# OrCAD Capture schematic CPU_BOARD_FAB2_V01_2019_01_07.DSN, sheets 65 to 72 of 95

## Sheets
65 053 COM-E_TYPE7_AB_1: size B
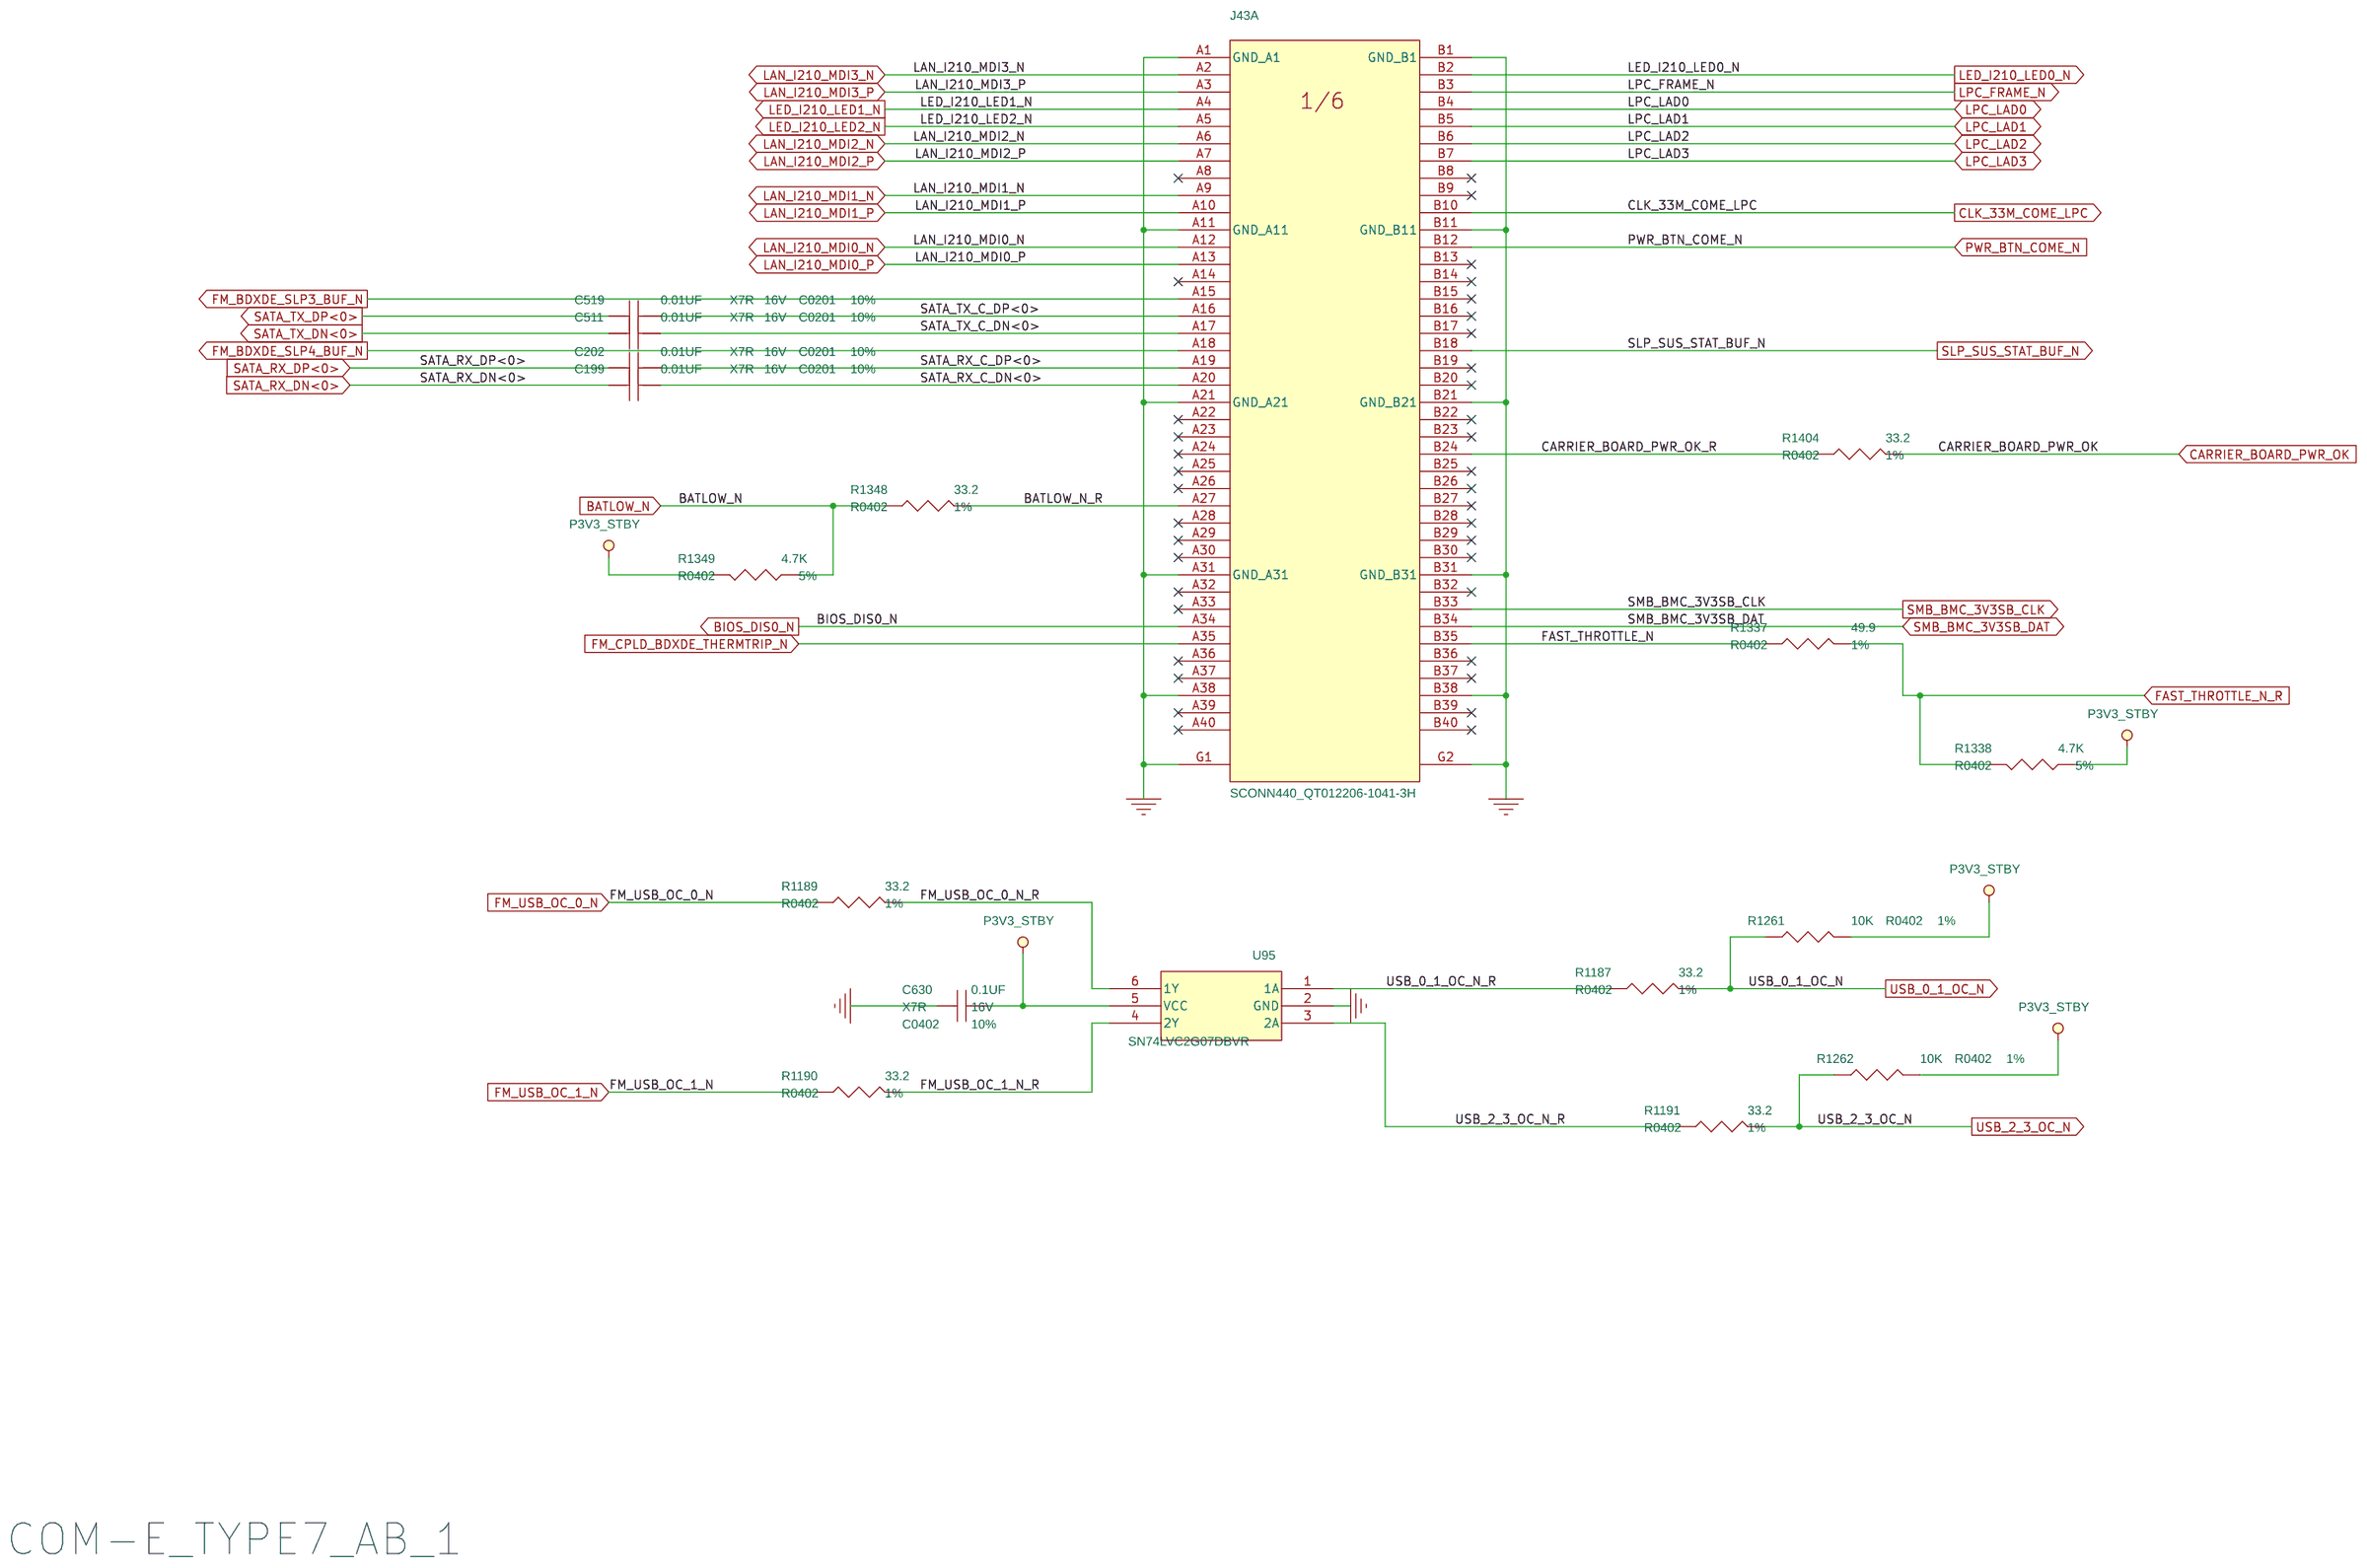
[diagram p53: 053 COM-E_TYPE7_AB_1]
66 055 COM-E_TYPE7_CD_1: size B
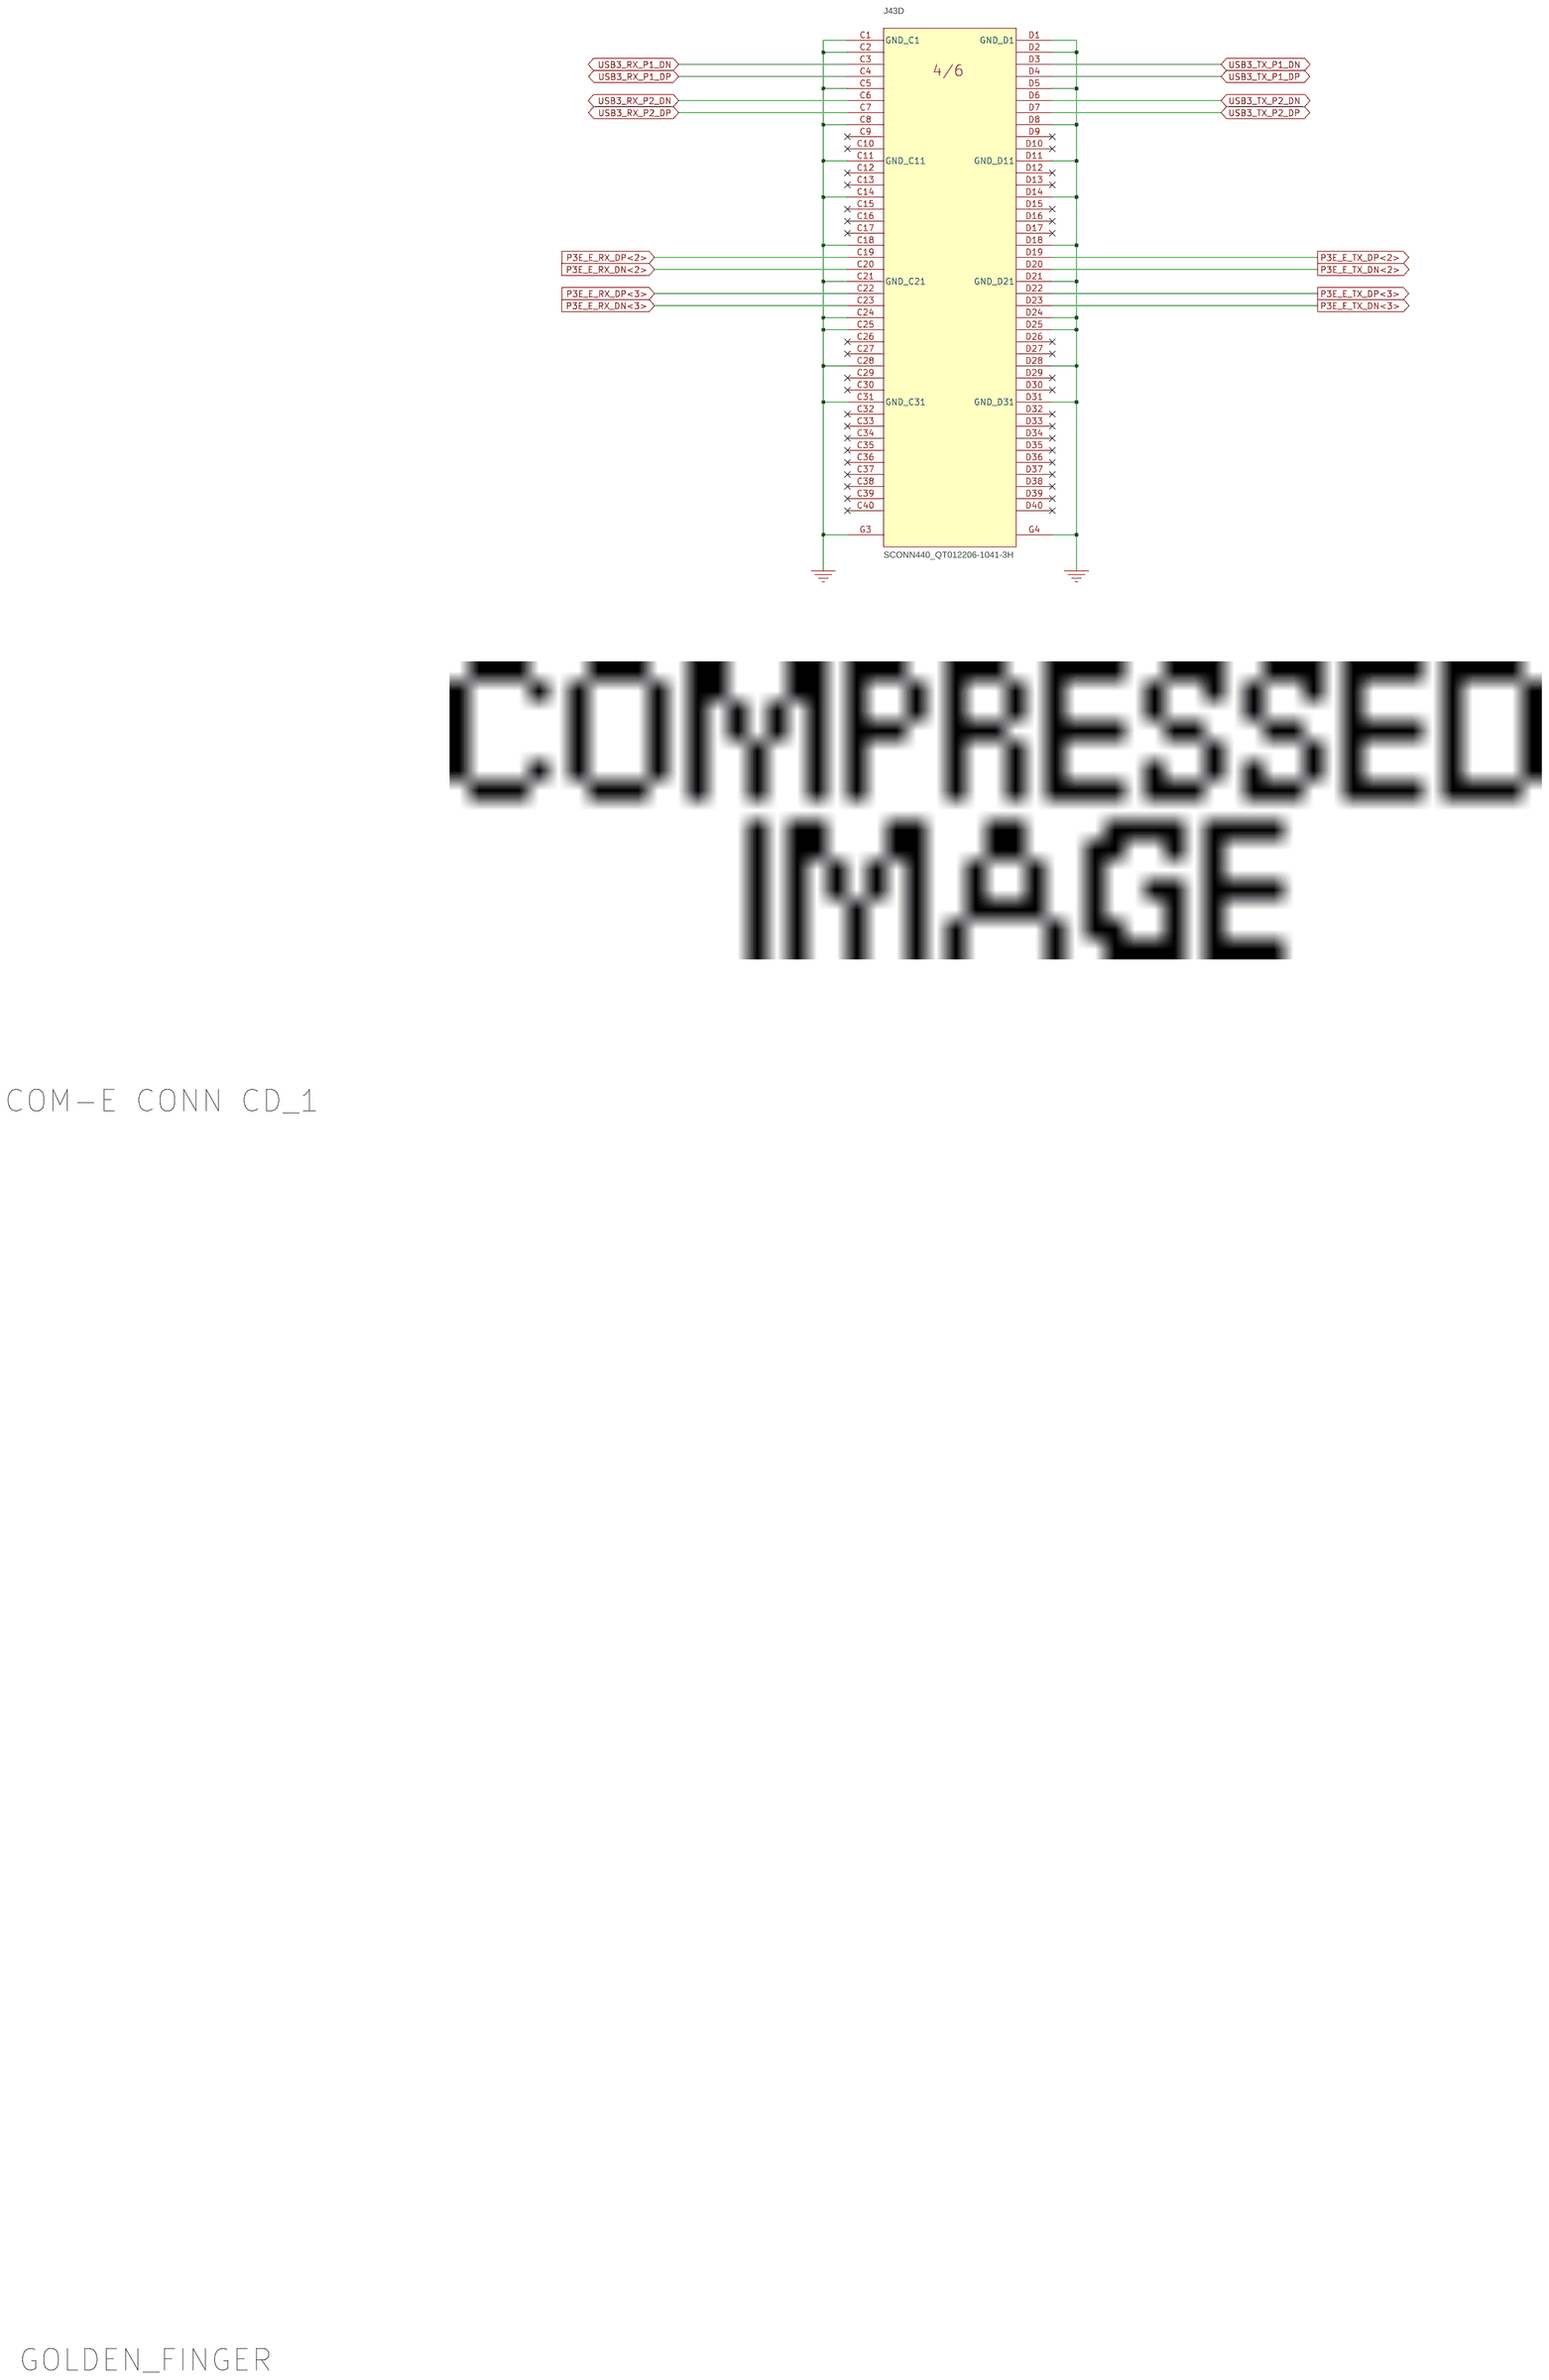
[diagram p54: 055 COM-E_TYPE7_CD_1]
67 057 LEVEL_SHIFT: size B
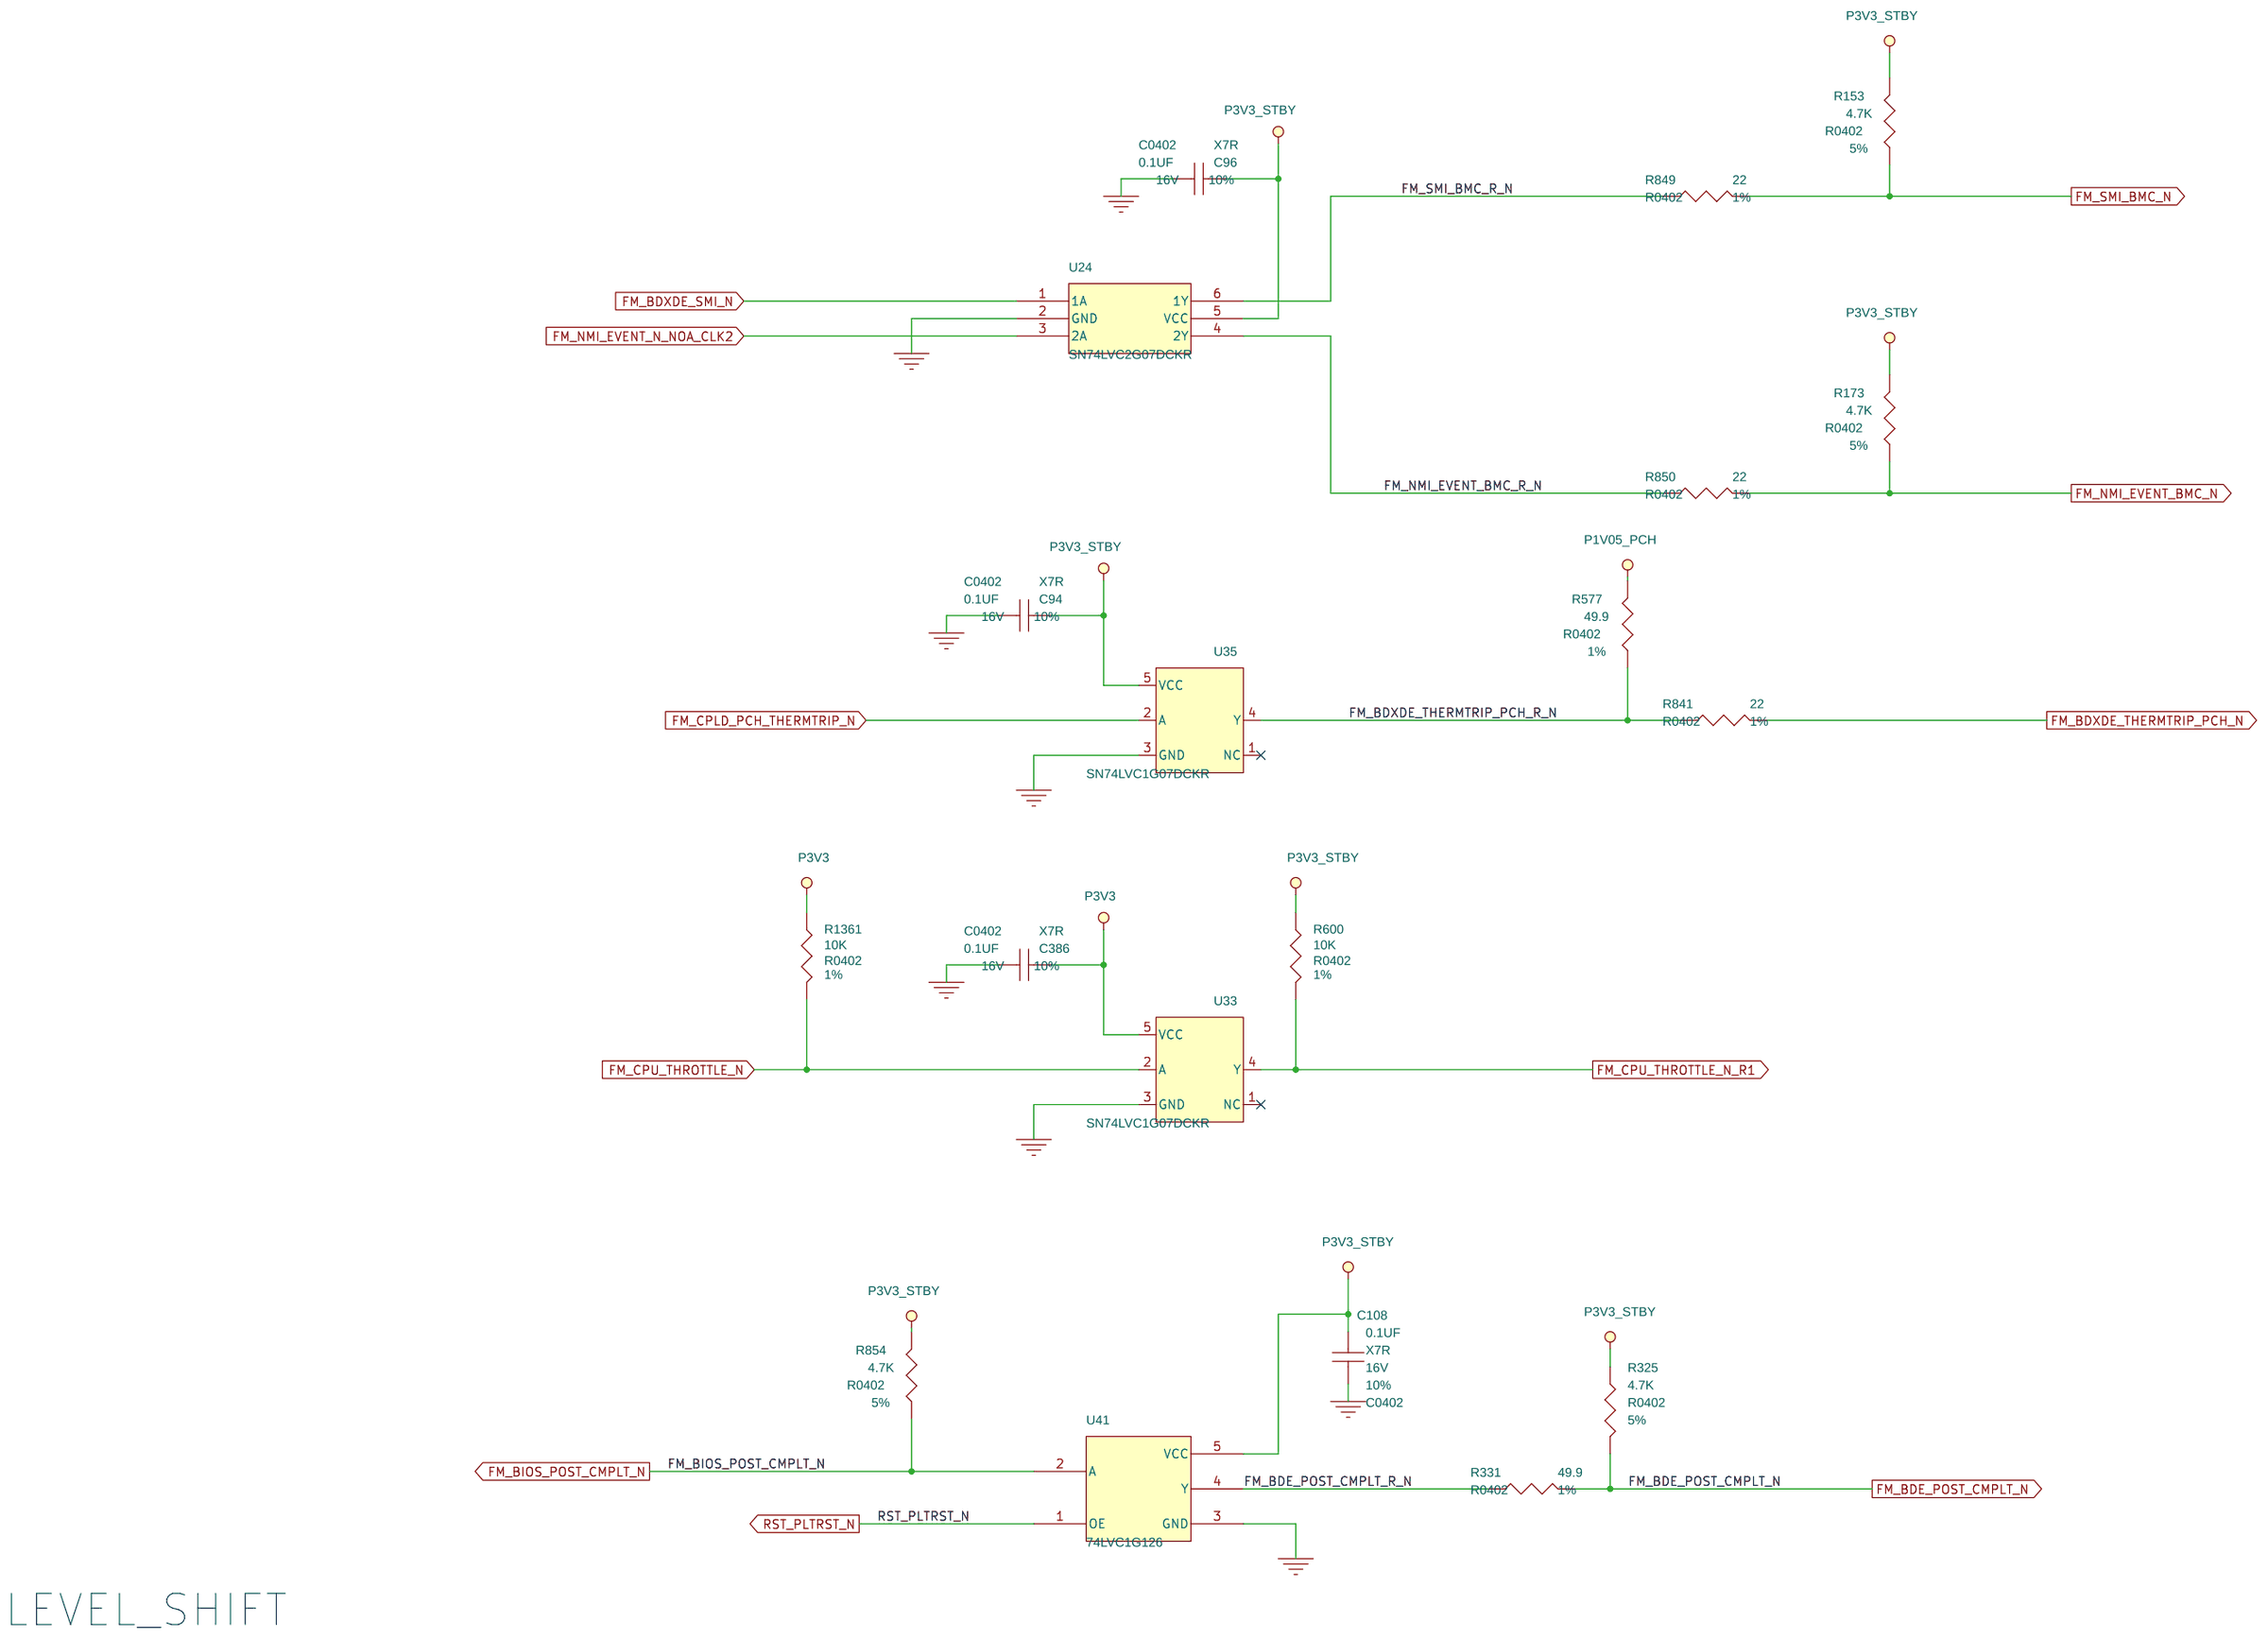
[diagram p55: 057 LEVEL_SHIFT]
68 058 SYS_SENSOR: size B
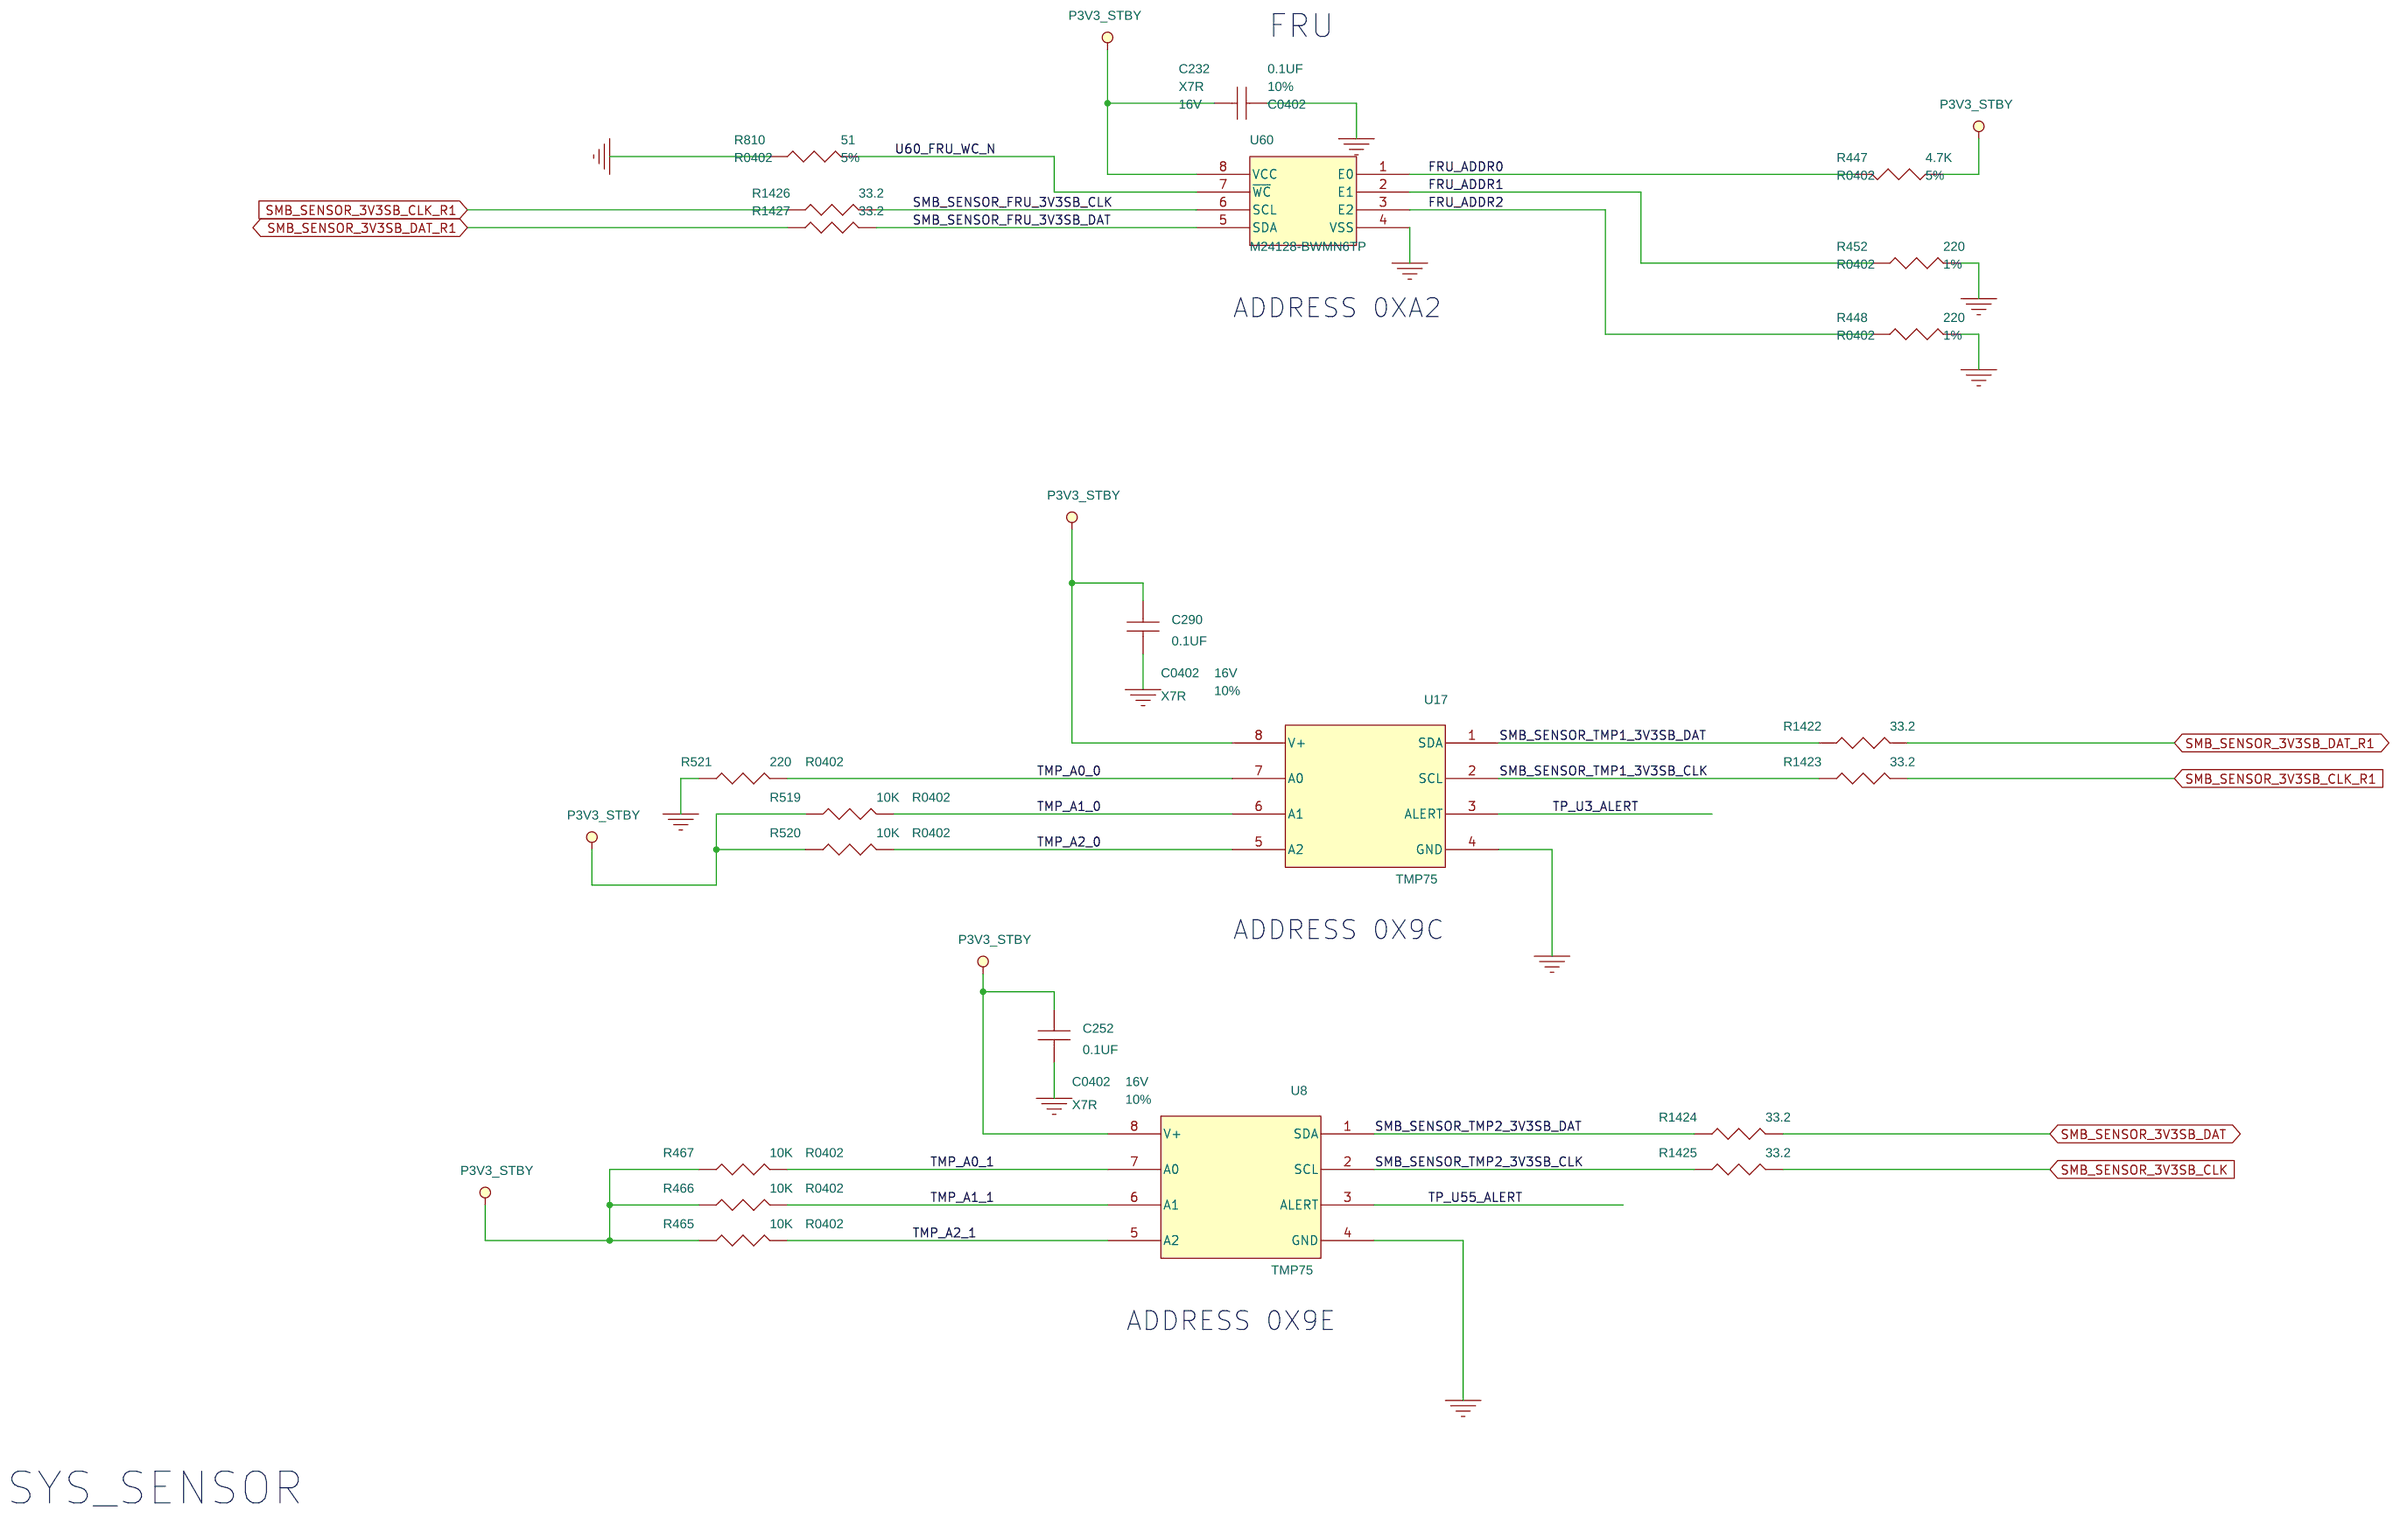
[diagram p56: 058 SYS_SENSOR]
69 059 PWR_SYSRST_BUTTON: size B
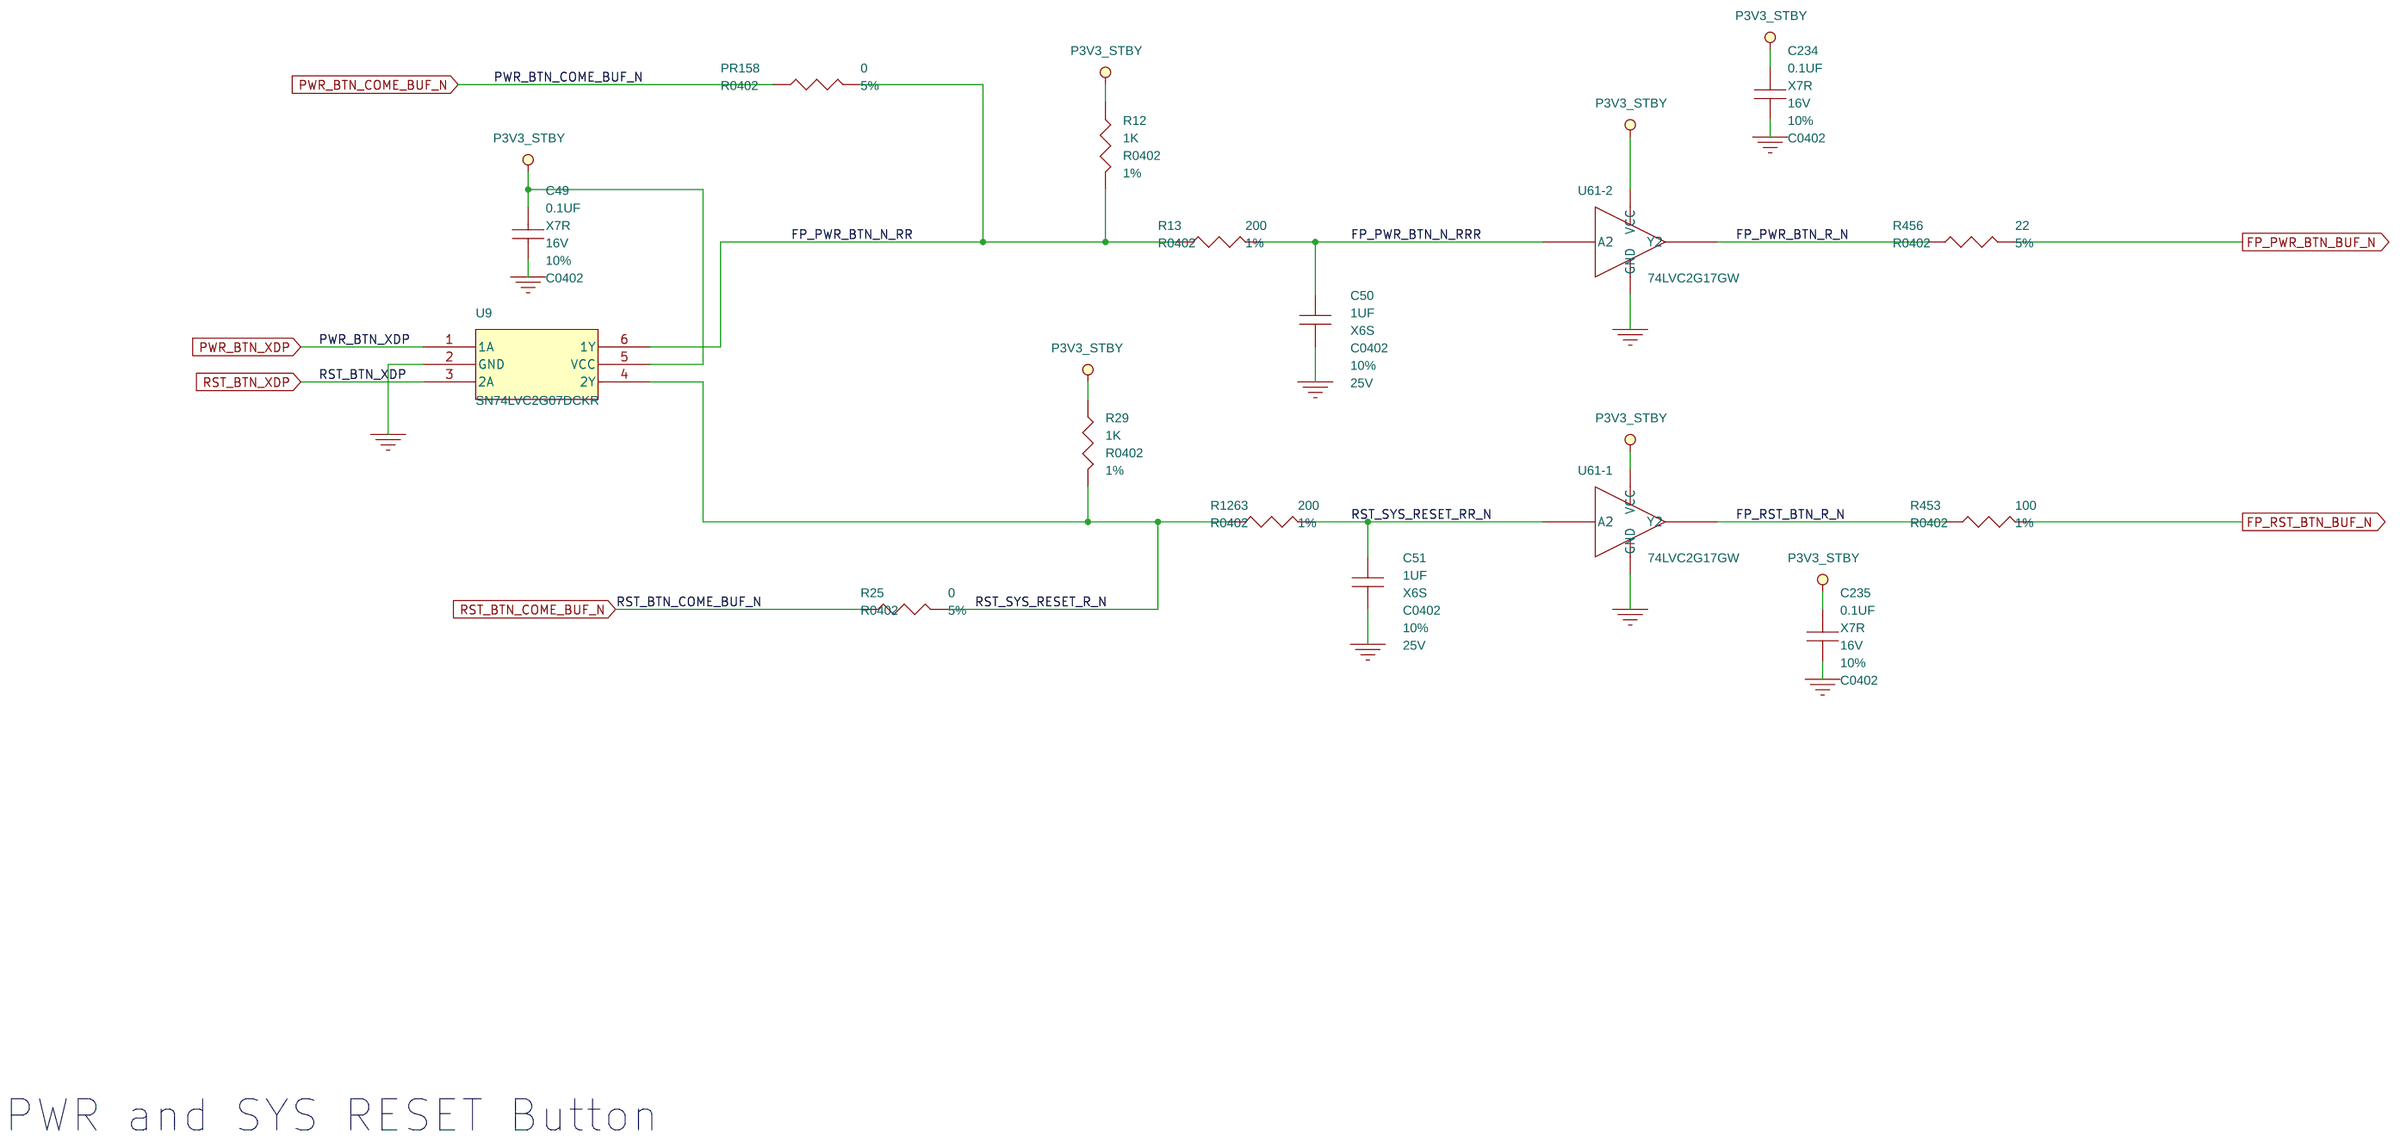
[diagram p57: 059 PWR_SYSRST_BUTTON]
70 060 DEBUG UART: size B
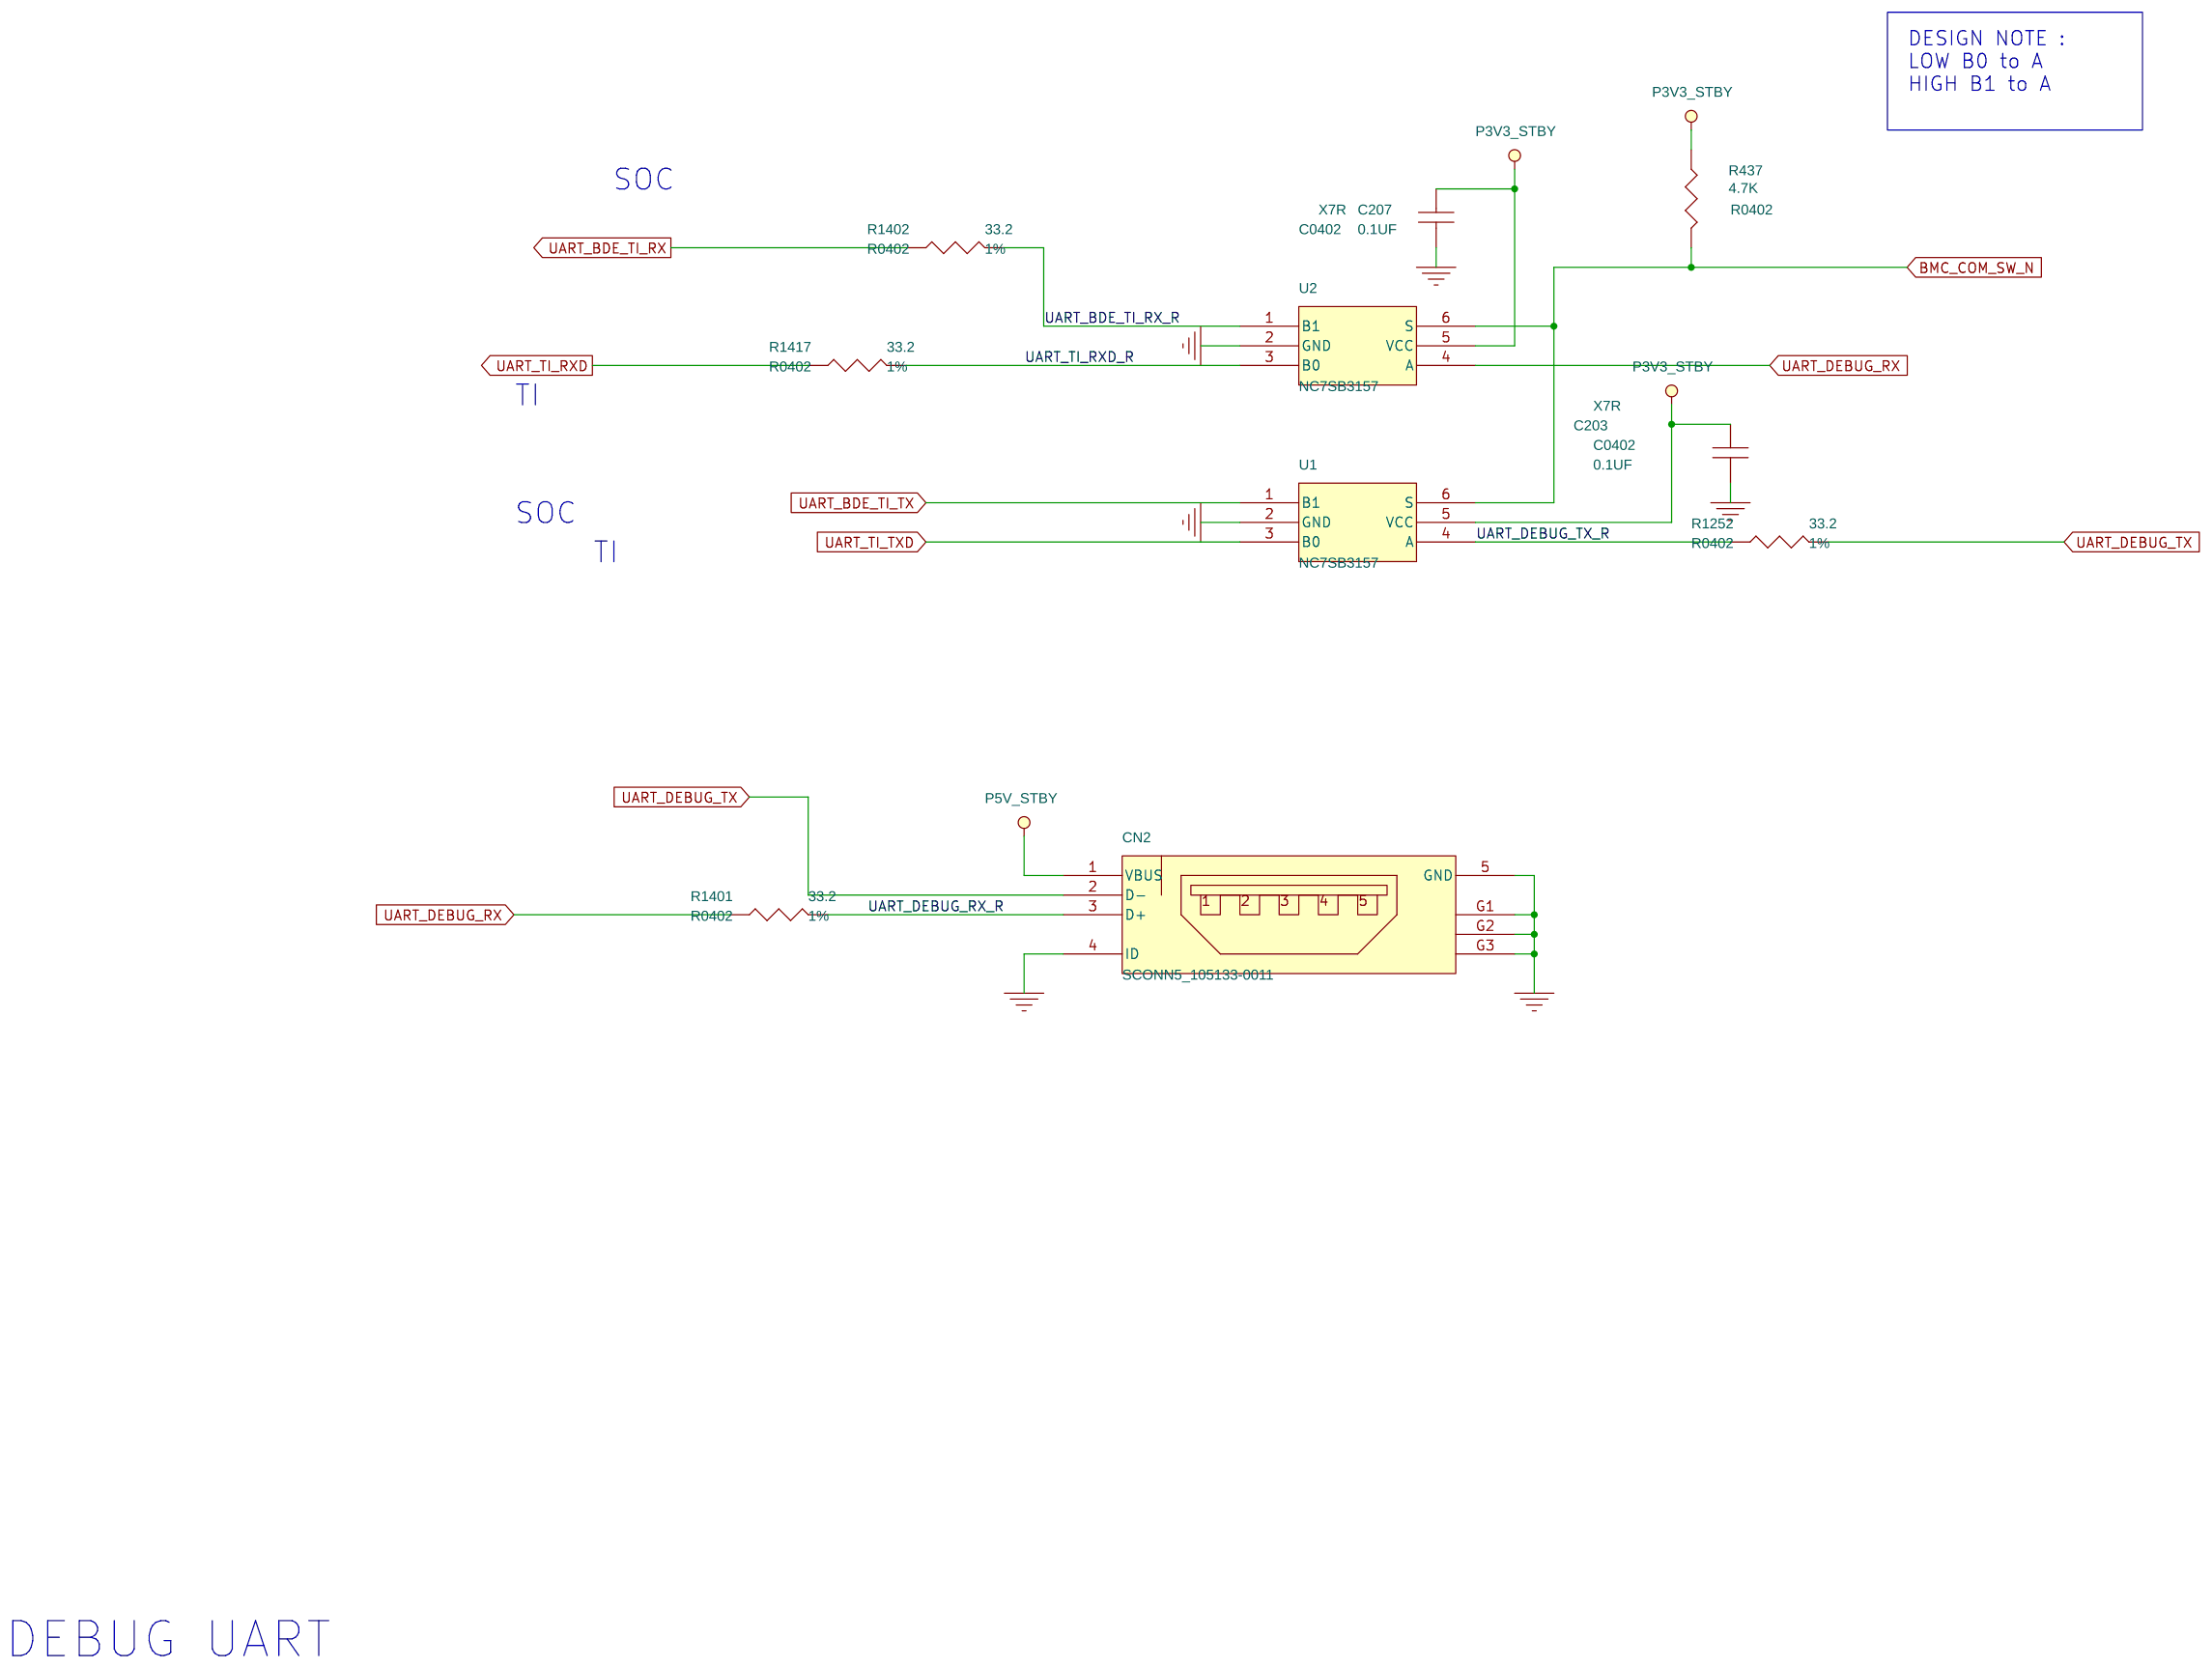
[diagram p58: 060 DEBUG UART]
71 061 SNOWFLAKE_1: size B
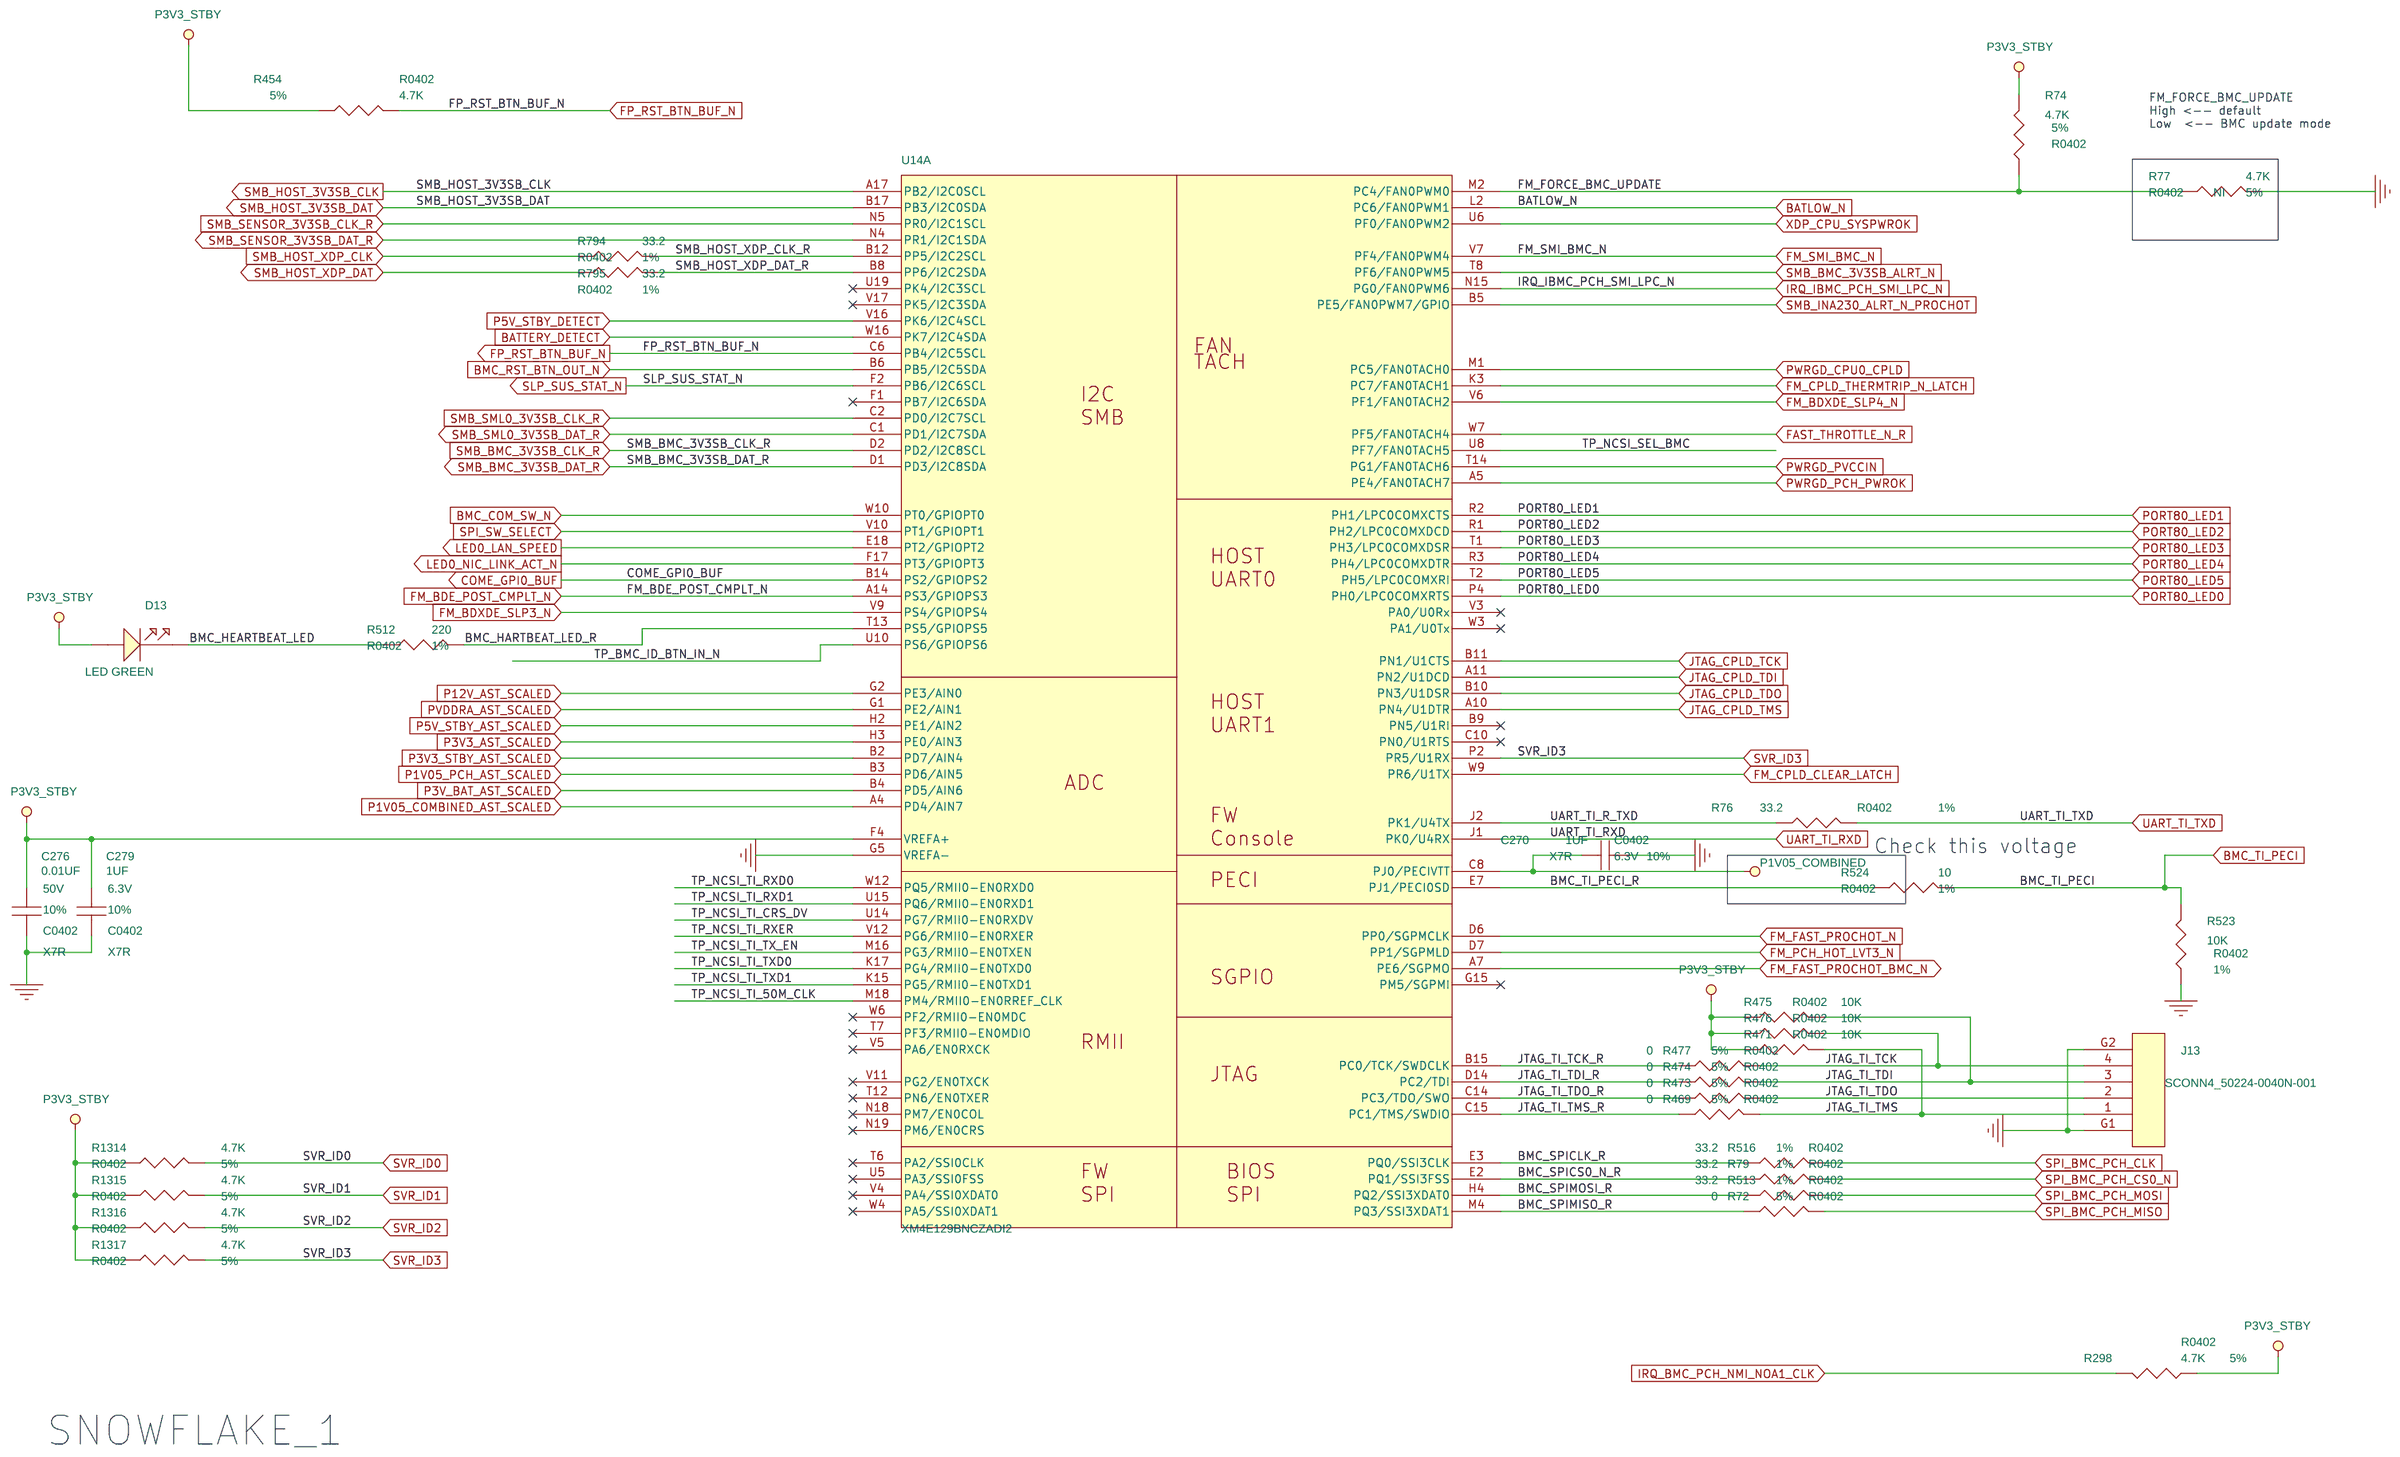
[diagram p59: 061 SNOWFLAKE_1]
72 062 SNOWFLAKE_2: size B
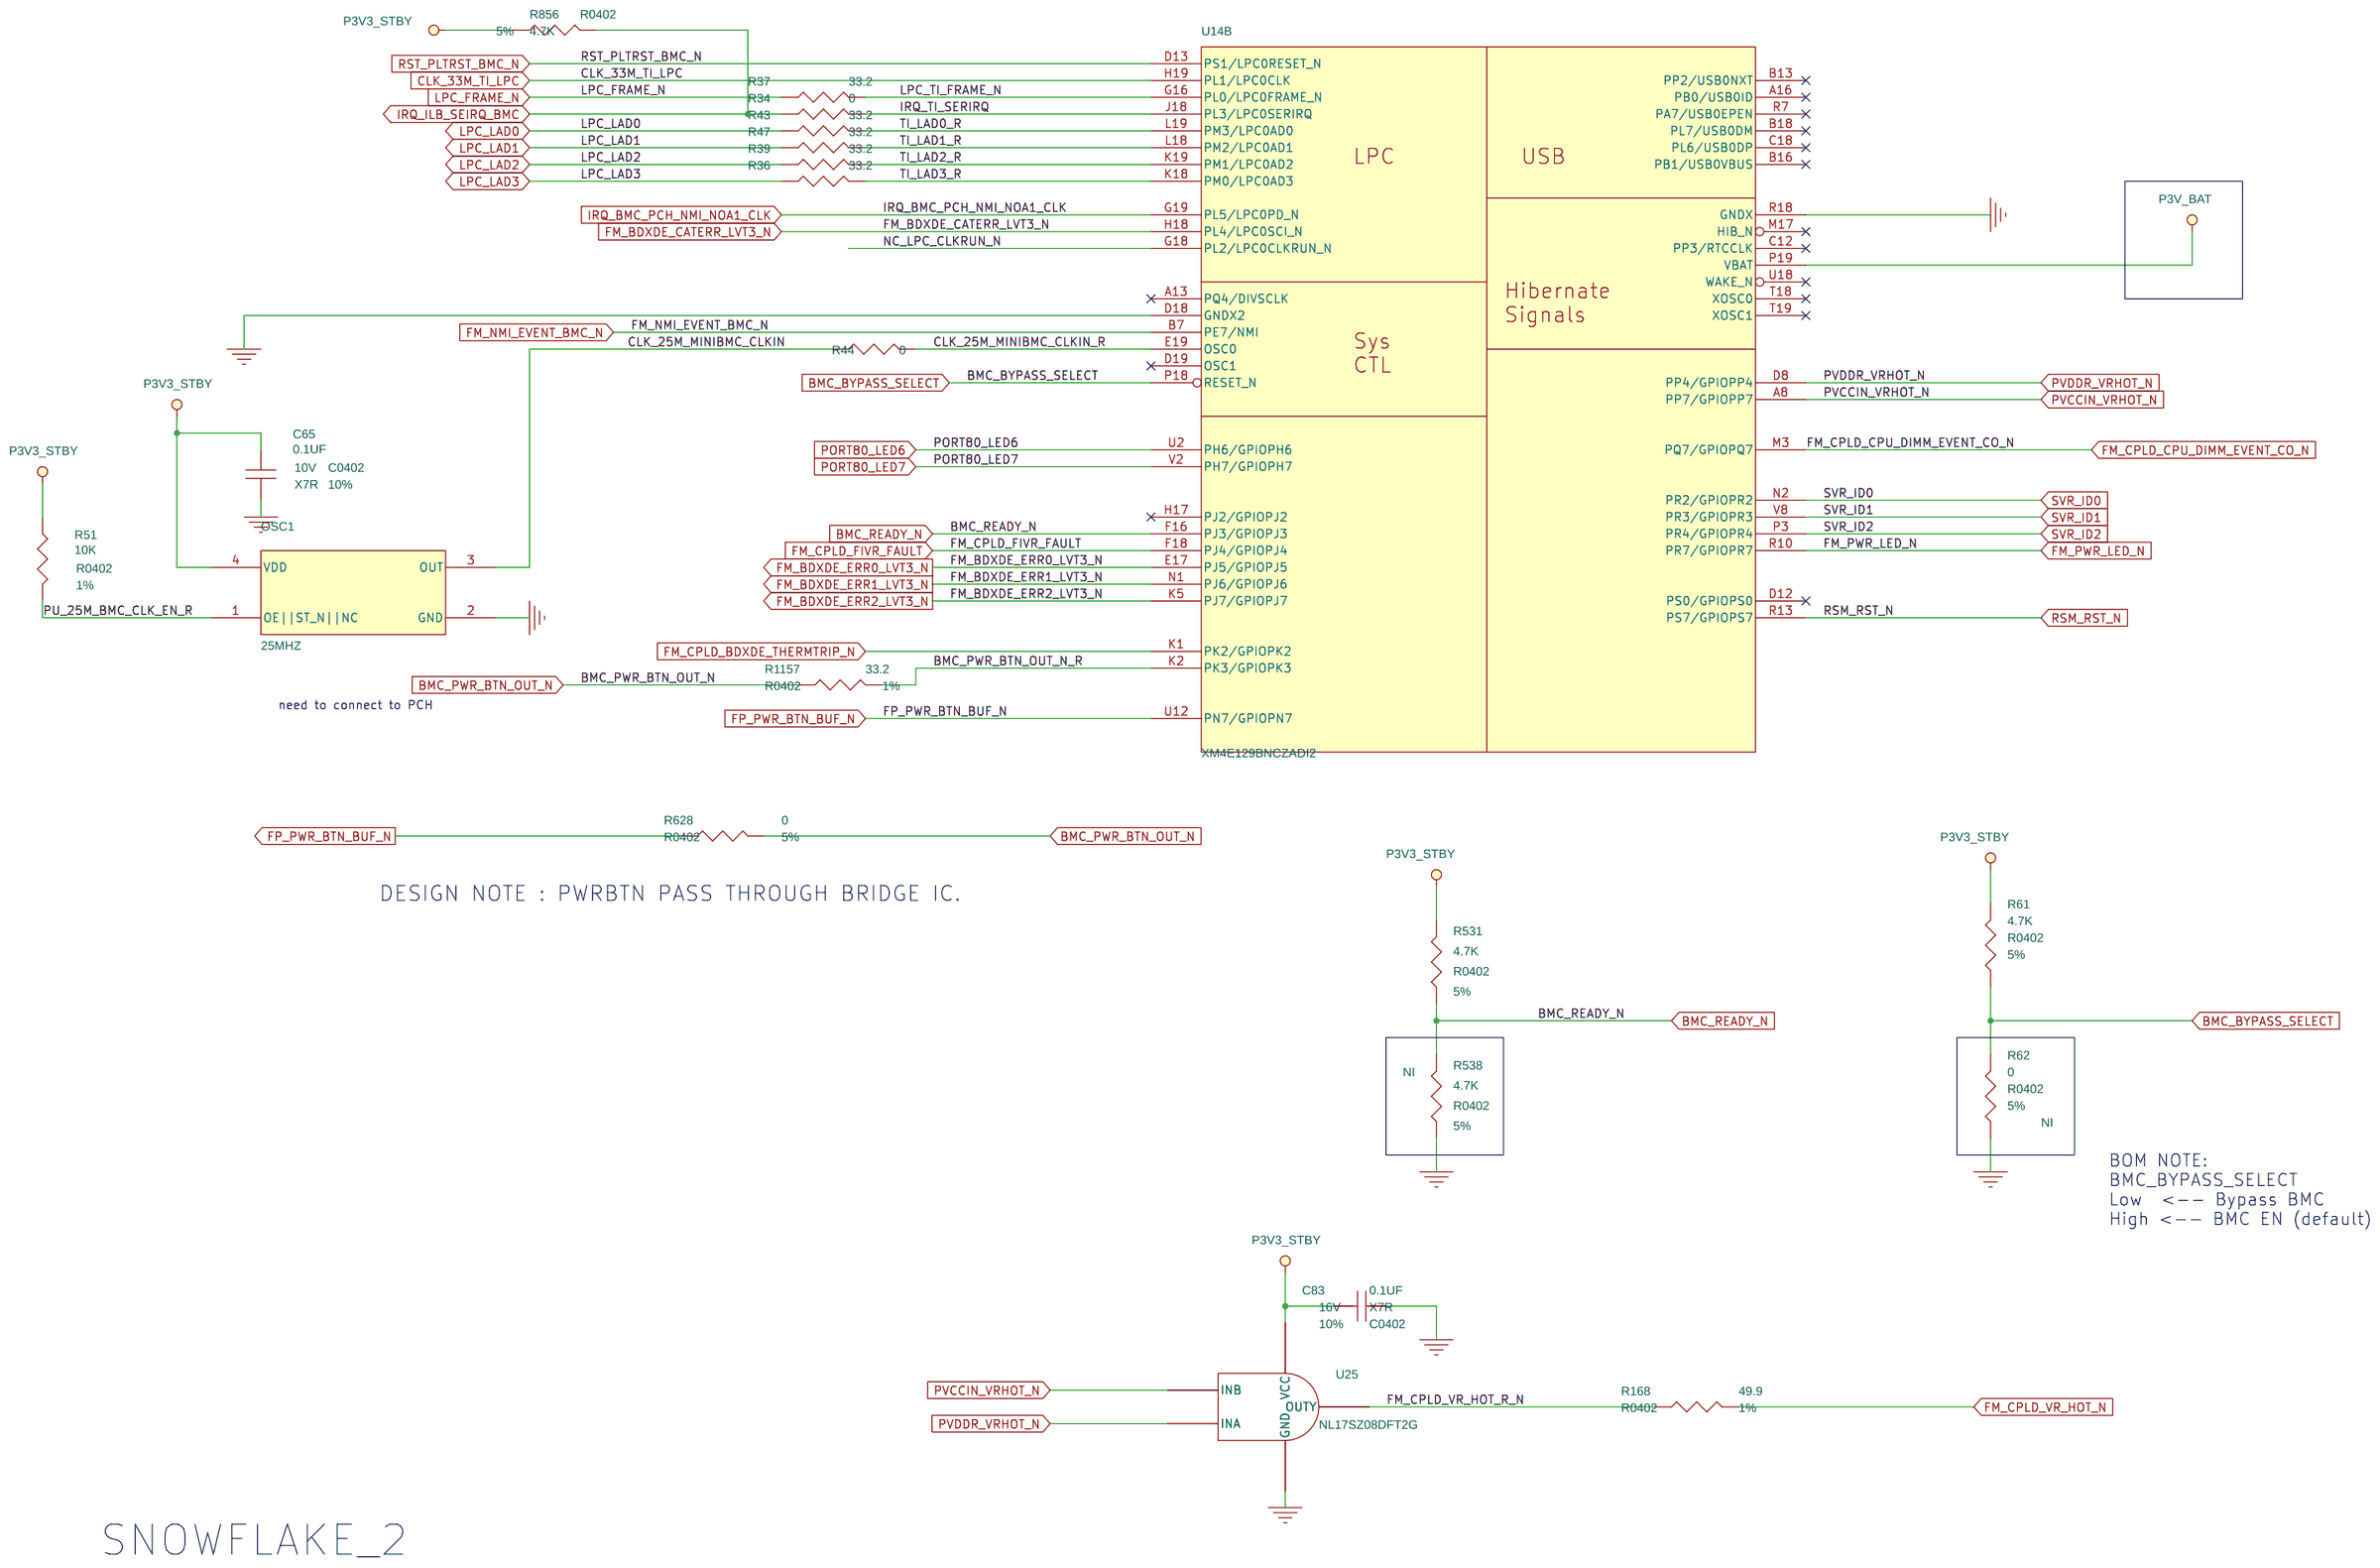
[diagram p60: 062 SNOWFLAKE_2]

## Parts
sheet 053 COM-E_TYPE7_AB_1
C199  0.01UF  [C0201]
C202  0.01UF  [C0201]
C511  0.01UF  [C0201]
C519  0.01UF  [C0201]
C630  0.1UF  [C0402]
R1187  33.2  [R0402]
R1189  33.2  [R0402]
R1190  33.2  [R0402]
R1191  33.2  [R0402]
R1261  10K  [R0402]
R1262  10K  [R0402]
R1337  49.9  [R0402]
R1338  4.7K  [R0402]
R1348  33.2  [R0402]
R1349  4.7K  [R0402]
R1404  33.2  [R0402]
U95  SN74LVC2G07DBVR  [SOT23-6XD]
sheet 055 COM-E_TYPE7_CD_1
J43  SCONN440_QT012206-1041-3H  [CON_440S4H4D4S_P0-5_LUH]  (sections A,B,C,D,E,F)
sheet 057 LEVEL_SHIFT
C94  0.1UF  [C0402]
C96  0.1UF  [C0402]
C108  0.1UF  [C0402]
C386  0.1UF  [C0402]
R153  4.7K  [R0402]
R173  4.7K  [R0402]
R325  4.7K  [R0402]
R331  49.9  [R0402]
R577  49.9  [R0402]
R600  10K  [R0402]
R841  22  [R0402]
R849  22  [R0402]
R850  22  [R0402]
R854  4.7K  [R0402]
R1361  10K  [R0402]
U24  SN74LVC2G07DCKR  [SC70-6]
U33  SN74LVC1G07DCKR  [SC70-5XB]
U35  SN74LVC1G07DCKR  [SC70-5XB]
U41  74LVC1G126  [SOT353_Q]
sheet 058 SYS_SENSOR
C232  0.1UF  [C0402]
C252  0.1UF  [C0402]
C290  0.1UF  [C0402]
R447  4.7K  [R0402]
R448  220  [R0402]
R452  220  [R0402]
R465  10K  [R0402]
R466  10K  [R0402]
R467  10K  [R0402]
R519  10K  [R0402]
R520  10K  [R0402]
R521  220  [R0402]
R810  51  [R0402]
R1422  33.2  [R0402]
R1423  33.2  [R0402]
R1424  33.2  [R0402]
R1425  33.2  [R0402]
R1426  33.2  [R0402]
R1427  33.2  [R0402]
U8  TMP75  [MSOP8]
U17  TMP75  [MSOP8]
U60  M24128-BWMN6TP  [SOIC8XH]
sheet 059 PWR_SYSRST_BUTTON
C49  0.1UF  [C0402]
C50  1UF  [C0402]
C51  1UF  [C0402]
C234  0.1UF  [C0402]
C235  0.1UF  [C0402]
PR158  0  [R0402]
R12  1K  [R0402]
R13  200  [R0402]
R25  0  [R0402]
R29  1K  [R0402]
R453  100  [R0402]
R456  22  [R0402]
R1263  200  [R0402]
U9  SN74LVC2G07DCKR  [SC70-6]
U61  74LVC2G17GW  [SOT363]  (sections -1,-2)
sheet 060 DEBUG UART
C203  0.1UF  [C0402]
C207  0.1UF  [C0402]
CN2  SCONN5_105133-0011  [USB1XAY]
R437  4.7K  [R0402]
R1252  33.2  [R0402]
R1401  33.2  [R0402]
R1402  33.2  [R0402]
R1417  33.2  [R0402]
U1  NC7SB3157  [SC70-6]
U2  NC7SB3157  [SC70-6]
sheet 061 SNOWFLAKE_1
C270  1UF  [C0402]
C276  0.01UF  [C0402]
C279  1UF  [C0402]
D13  LED GREEN  [LED2S_0402]
J13  SCONN4_50224-0040N-001  [CON_4S1H2S_P1XC]
R72  0  [R0402]
R74  4.7K  [R0402]
R76  33.2  [R0402]
R77  4.7K  [R0402]
R79  33.2  [R0402]
R298  4.7K  [R0402]
R454  4.7K  [R0402]
R469  0  [R0402]
R471  10K  [R0402]
R473  0  [R0402]
R474  0  [R0402]
R475  10K  [R0402]
R476  10K  [R0402]
R477  0  [R0402]
R512  220  [R0402]
R513  33.2  [R0402]
R516  33.2  [R0402]
R523  10K  [R0402]
R524  10  [R0402]
R794  33.2  [R0402]
R795  33.2  [R0402]
R1314  4.7K  [R0402]
R1315  4.7K  [R0402]
R1316  4.7K  [R0402]
R1317  4.7K  [R0402]
sheet 062 SNOWFLAKE_2
C65  0.1UF  [C0402]
C83  0.1UF  [C0402]
OSC1  25MHZ  [OSC4S_SIT1602BI_2X1-6]
R34  0  [R0402]
R36  33.2  [R0402]
R37  33.2  [R0402]
R39  33.2  [R0402]
R43  33.2  [R0402]
R44  0  [R0402]
R47  33.2  [R0402]
R51  10K  [R0402]
R61  4.7K  [R0402]
R62  0  [R0402]
R168  49.9  [R0402]
R531  4.7K  [R0402]
R538  4.7K  [R0402]
R628  0  [R0402]
R856  4.7K  [R0402]
R1157  33.2  [R0402]
U25  NL17SZ08DFT2G  [SC70-5XA]
sheet 063 SNOWFLAKE_3
U14  XM4E129BNCZADI2  [BGA212]  (sections A,B,C)

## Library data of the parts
C199 C202 C511 C519 = CAP_NP: CAP CHIP 0.01U 16V(+-10%.X7R.0201); CLASS: DISCRETE; CMPLS_LVL: EP_Tmp; Data: YGO_CA-CC-SC SERIES.pdf; EE_CHECK_LIST: C0201.xls; From_pj: LU1-ROGER; Lifecycle: Comp-Approve; MATERIAL: X7R; Manuf_PN: CC0201X103K1OST-S; Manuf_name: YAGEO CORPORATION; Manufacturer: AVX; Manuftr: YGO; Part_Type: *LF_C0201; Standard: ##; TOLERANCE: 10%; TOP_BOT: BOT; VOLTAGE: 16V; fp_ECN: DCN-all 0201 RCL part.doc
C630 = CAP_NP: CAP CHIP 0.1U 16V(10%.X7R.0402); CLASS: DISCRETE; CMPLS_LVL: EP(V1); Data: MUR_LF_CAP SERIES_1.pdf; From_pj: S5A-TRAVIS; Lifecycle: Comp-Approve; MATERIAL: X7R; Manuf_PN: WBM155R71C104K; Manuf_name: MURATA ERIE N.A. INC TAIWAN BRANCH Okayama Murata Mfg.Co..Ltd. Wakura Murata Mfg; Manufacturer: AVX; Manuftr: MUR; Part_Type: *LF_C0402; RD_CMPLS_LVL: EP(V1); TOLERANCE: 10%; Top_Bot: BOT; VOLTAGE: 16V; fp_ECN: 0402 SERIES_LL34.xls
R36 R37 R39 R43 R47 R79 R513 R516 R1157 R1187 R1189-R1191 R1252 R1348 R1401 R1402 R1404 R1417 R1422-R1427 = R: RES CHIP 33.2 1/16W +-1%(0402); CLASS: DISCRETE; CMPLS_LVL: EP; Data: CYN_LF_RL SERIES.pdf; From_pj: A06-EDISON; Lifecycle: Comp-Approve; MATERIAL: CHIP; Manuf_PN: RR0510S-33R2-FN; Manuf_name: CYNTEC CO.. LTD.; Manuftr: CYN; Part_Type: *LF_Resistor; TOLERANCE: 1%; WATTAGE: 1/16W; fp_ECN: 0402 SERIES_LL34.xls
R51 R471 R475 R476 R600 R1261 R1262 R1361 = R: RES CHIP 10K 1/16W +-1% (0402); CLASS: DISCRETE; CMPLS_LVL: EP; Data: WTC_LF_WR SERIES.pdf; From_pj: S82; Lifecycle: Comp-Approve; MATERIAL: CHIP; Manuf_PN: RR0510S-103-FN; Manuf_name: CYNTEC CO.. LTD.; Manuftr: CYN; Part_Type: *LF_Resistor; Status: Preferred; TOLERANCE: 1%; WATTAGE: 1/16W; fp_ECN: 0402 SERIES_LL34.xls
R168 R331 R577 R1337 = R: RES CHIP 49.9 1/16W +-1% (0402); CLASS: DISCRETE; CMPLS_LVL: EP; Data: WTC_LF_WR SERIES.pdf; Lifecycle: Comp-Approve; MATERIAL: CHIP; Manuf_PN: RR0510S-49R9-FN; Manuf_name: CYNTEC CO.. LTD.; Manuftr: CYN; Part_Type: *LF_Resistor; Status: Preferred; TOLERANCE: 1%; WATTAGE: 1/16W; fp_ECN: 0402 SERIES_LL34.xls
R61 R1338 R1349 = R: RES CHIP 4.7K 1/16W +-5% (0402); BOM: TI; CLASS: DISCRETE; CMPLS_LVL: EP; Data: WTC_LF_WR SERIES.pdf; Lifecycle: Comp-Approve; MATERIAL: CHIP; Manuf_PN: RR0510S-472-JN; Manuf_name: CYNTEC CO.. LTD.; Manuftr: CYN; Part_Type: *LF_Resistor; Status: Preferred; TOLERANCE: 5%; WATTAGE: 1/16W; fp_ECN: 0402 SERIES_LL34.xls
U95 = SN74LVC2G07DBVR: IC OTHER(6P) SN74LVC2G07DBVR(SOT23); CLASS: IC; CMPLS_LVL: EP(V1); Data: TIC_SN74LVC2G07_rev2006.pdf; From_pj: S1VA-CHRIS; Lifecycle: Comp-Approve; MATERIAL: IC; Manuf_name: TEXAS INSTRUMENTS SUPPLY CO.,; Manuftr: TIC; Part_Type: *LF_Chipset; RD_CMPLS_LVL: EP(V1); Standard: Potential
J43 = SCONN440_QT01220610413H: CONN SMD HOUSING 440P 4R FS(P0.5,H3.25); CLASS: IO; Data: FOX_QT012206-1041-3H.pdf; From_pj: F0B-WILLIAM; Lifecycle: Comp-Release Qty; MATERIAL: IO; Manuf_PN: QT012206-1041-3H; Manuf_name: (FOXCONN) HON HAI PRECISION INDUSTRY KANG ZHUN PRESION TOOLING(KUN SHAN)CO..LTD; Manuftr: FOX; Part_Type: *LF_Connector; RD_CMPLS_LVL: EP(V1); Standard: Non-Preferred
C94 C96 C108 C386 = CAP_NP: CAP CHIP 0.1U 16V(10%.X7R.0402); CLASS: DISCRETE; CMPLS_LVL: EP(V1); Data: MUR_LF_CAP SERIES_1.pdf; From_pj: S5A-TRAVIS; Lifecycle: Comp-Approve; MATERIAL: X7R; Manuf_PN: WBM155R71C104K; Manuf_name: MURATA ERIE N.A. INC TAIWAN BRANCH Okayama Murata Mfg.Co..Ltd. Wakura Murata Mfg; Manufacturer: MUR; Manuftr: MUR; Part_Type: *LF_C0402; RD_CMPLS_LVL: EP(V1); TOLERANCE: 10%; VOLTAGE: 16V; fp_ECN: 0402 SERIES_LL34.xls; top_bot: TOP
R153 R173 R437 R854 R856 R1314-R1317 = R: RES CHIP 4.7K 1/16W +-5% (0402); CLASS: DISCRETE; CMPLS_LVL: EP; Data: WTC_LF_WR SERIES.pdf; Lifecycle: Comp-Approve; MATERIAL: CHIP; Manuf_PN: RR0510S-472-JN; Manuf_name: CYNTEC CO.. LTD.; Manuftr: CYN; Part_Type: *LF_Resistor; Status: Preferred; TOLERANCE: 5%; WATTAGE: 1/16W; fp_ECN: 0402 SERIES_LL34.xls
R325 R447 = R: RES CHIP 4.7K 1/16W +-5% (0402); CLASS: DISCRETE; CMPLS_LVL: EP; Data: WTC_LF_WR SERIES.pdf; Lifecycle: Comp-Approve; MATERIAL: CHIP; Manuf_PN: RR0510S-472-JN; Manuf_name: CYNTEC CO.. LTD.; Manufacturer: CYN; Manuftr: CYN; Part_Type: *LF_Resistor; Status: Preferred; TOLERANCE: 5%; WATTAGE: 1/16W; fp_ECN: 0402 SERIES_LL34.xls; top_bot: BOT
R841 R849 R850 = R: RES CHIP 22 1/16W +-1%(0402); CLASS: DISCRETE; CMPLS_LVL: EP; Data: RHT_LF_RES SERIES-2.pdf; From_pj: S75-L.A.; Lifecycle: Comp-Approve; MATERIAL: CHIP; Manuf_PN: CR0222R0F002S; Manuf_name: RTECH TECHNOLOGY CO..LTD. (Compostar); Manuftr: RHT; Part_Type: *LF_Resistor; Standard: ##; Status: Preferred; TOLERANCE: 1%; WATTAGE: 1/16W; fp_ECN: 0402 SERIES_LL34.xls
U9 U24 = SN74LVC2G07DCKR: IC(6P) SN74LVC2G07DCKR(SC70-6); CLASS: IC; CMPLS_LVL: EP(V1); Data: SN74LVC2G07.pdf; From_pj: S2RS-WIN; Lifecycle: Comp-Approve; MATERIAL: IC; Manuf_name: TEXAS INSTRUMENTS SUPPLY CO..; Manuftr: TIC; Part_Type: *LF_Chipset; RD_CMPLS_LVL: EP(V1); Standard: Potential
U33 U35 = SN74LVC1G07: IC OTHER(5P)SN74LVC1G07DCKR(SOT); CLASS: IC; CMPLS_LVL: EP(V1); Data: TIC_SN74LVC1G07DCKR.pdf; From_pj: S50-STEVE; Lifecycle: Comp-Approve; MATERIAL: IC; Manuf_name: TEXAS INSTRUMENTS SUPPLY CO..; Manufacturer: TIC; Manuftr: TIC; Part_Type: *LF_Chipset; RD_CMPLS_LVL: EP(V1); Standard: Potential
U41 = 74LVC1G126: IC(5P) 74LVC1G126GW (SC-88A) EP; CLASS: IC; CMPLS_LVL: EP; Data: PHI_74LVC1G126.pdf; From_pj: S90-ROX; Lifecycle: Comp-Approve; MATERIAL: IC; Manuf_PN: 74LVC1G126GW; Manuf_name: PHILIPS TAIWAN LTD..; Manuftr: PHI; Part_Type: *LF_Chipset
C232 = CAP_NP: CAP CHIP 0.1U 16V(10%.X7R.0402); CLASS: DISCRETE; CMPLS_LVL: EP(V1); Data: MUR_LF_CAP SERIES_1.pdf; From_pj: S5A-TRAVIS; Lifecycle: Comp-Approve; MATERIAL: X7R; Manuf_PN: WBM155R71C104K; Manuf_name: MURATA ERIE N.A. INC TAIWAN BRANCH Okayama Murata Mfg.Co..Ltd. Wakura Murata Mfg; Manuftr: MUR; Part_Type: *LF_C0402; RD_CMPLS_LVL: EP(V1); TOLERANCE: 10%; VOLTAGE: 16V; fp_ECN: 0402 SERIES_LL34.xls
C83 C252 C290 = CAP_NP: CAP CHIP 0.1U 16V(10%.X7R.0402); CLASS: DISCRETE; CMPLS_LVL: EP(V1); Data: MUR_LF_CAP SERIES_1.pdf; From_pj: S5A-TRAVIS; Lifecycle: Comp-Approve; MATERIAL: X7R; Manuf_PN: WBM155R71C104K; Manuf_name: MURATA ERIE N.A. INC TAIWAN BRANCH Okayama Murata Mfg.Co..Ltd. Wakura Murata Mfg; Manufacturer: MUR; Manuftr: MUR; Part_Type: *LF_C0402; RD_CMPLS_LVL: EP(V1); TOLERANCE: 10%; VOLTAGE: 16V; fp_ECN: 0402 SERIES_LL34.xls
R448 R452 = R: RES CHIP 220 1/16W +-1%(0402); CLASS: DISCRETE; CMPLS_LVL: EP; Data: TAI_LF_RM SERIES-2.pdf; From_pj: S2F-JOSEPH; Lifecycle: Comp-Approve; MATERIAL: CHIP; Manuf_PN: RM04FTN2200; Manuf_name: TA-I TECHNOLOGY CO..LTD.; Manufacturer: CYN; Manuftr: TAI; Part_Type: *LF_Resistor; SUBSYS: HW_RES; TOLERANCE: 1%; TOP_BOT: BOT; WATTAGE: 1/16W; fp_ECN: 0402 SERIES_LL34.xls
R465-R467 R519 R520 = R: RES CHIP 10K 1/16W +-1% (0402); CLASS: DISCRETE; CMPLS_LVL: EP; Data: WTC_LF_WR SERIES.pdf; From_pj: S82; Lifecycle: Comp-Approve; MATERIAL: CHIP; Manuf_PN: RR0510S-103-FN; Manuf_name: CYNTEC CO.. LTD.; Manuftr: CYN; Part_Type: *LF_Resistor; Status: Preferred; TOLERANCE: 1%; TOP_BOT: TOP; WATTAGE: 1/16W; fp_ECN: 0402 SERIES_LL34.xls
R521 = R: RES CHIP 220 1/16W +-1%(0402); CLASS: DISCRETE; CMPLS_LVL: EP; Data: TAI_LF_RM SERIES-2.pdf; From_pj: S2F-JOSEPH; Lifecycle: Comp-Approve; MATERIAL: CHIP; Manuf_PN: RM04FTN2200; Manuf_name: TA-I TECHNOLOGY CO..LTD.; Manuftr: TAI; Part_Type: *LF_Resistor; TOLERANCE: 1%; TOP_BOT: TOP; WATTAGE: 1/16W; fp_ECN: 0402 SERIES_LL34.xls
R810 = R: RES CHIP 51 1/16W +-5%(0402); CLASS: DISCRETE; CMPLS_LVL: EP; Data: TAI_LF_RM SERIES.pdf; Lifecycle: Comp-Approve; MATERIAL: CHIP; Manuf_PN: RR0510S-510-JN; Manuf_name: CYNTEC CO.. LTD.; Manufacturer: CYN; Manuftr: CYN; Part_Type: *LF_Resistor; SUBSYS: HW_RES; Status: Preferred; TOLERANCE: 5%; TOP_BOT: BOT; WATTAGE: 1/16W; fp_ECN: 0402 SERIES_LL34.xls
U8 U17 = TMP75AIDGKR: IC(8P) TMP75AIDGKR (MSOP); CLASS: IC; CMPLS_LVL: EP; Data: TIC_TMP75-TMP175.pdf; From_pj: JN1-LUNG; Lifecycle: Comp-Approve; MATERIAL: IC; Manuf_name: TEXAS INSTRUMENTS SUPPLY CO..; Manuftr: TIC; Part_Type: *LF_Chipset; Standard: Non-Preferred
U60 = M24128: IC(8P) EEPROM M24128-BWMN6TP(SO8); CLASS: IC; CMPLS_LVL: EP; Data: SGT_M24256-B_M24128-B.pdf; From_pj: S2D-TERRY; Lifecycle: Comp-Approve; MATERIAL: IC; Manuf_name: SGS-THOMSON(STMicroelectronics); Manuftr: SGT; Part_Type: *LF_Chipset
C49 C234 C235 = CAP_NP: CAP CHIP 0.1U 16V(10%.X7R.0402); BOM: AST2300; CLASS: DISCRETE; CMPLS_LVL: EP(V1); Data: MUR_LF_CAP SERIES_1.pdf; From_pj: S5A-TRAVIS; Lifecycle: Comp-Approve; MATERIAL: X7R; Manuf_PN: WBM155R71C104K; Manuf_name: MURATA ERIE N.A. INC TAIWAN BRANCH Okayama Murata Mfg.Co..Ltd. Wakura Murata Mfg; Manuftr: MUR; Part_Type: *LF_C0402; RD_CMPLS_LVL: EP(V1); TOLERANCE: 10%; VOLTAGE: 16V; fp_ECN: 0402 SERIES_LL34.xls
C50 C51 = CAP_NP: CAP CHIP 1UF 25V(+-10%,X6S,0402); CLASS: DISCRETE; CMPLS_LVL: EP(V1); Data: MUR_GRM155R72A221KA01-01.pdf; From_pj: F06-RAYMOND; Lifecycle: Comp-Approve; MATERIAL: X6S; Manuf_PN: GRM155C81E105K; Manuf_name: MURATA ERIE N.A. INC TAIWAN BRANCH Okayama Murata Mfg.Co..Ltd.Wakura Murata Mfg.; Manuftr: MUR; Part_Type: *LF_C0402; RD_CMPLS_LVL: EP(V1); TOLERANCE: 10%; VOLTAGE: 25V; fp_ECN: 0402 SERIES_LL34.xls
PR158 R25 R34 R44 R72 R469 R473 R474 R477 R628 = R: RESISTOR CHIP 0 1/16W +-5%(0402); CLASS: DISCRETE; CMPLS_LVL: EP; Data: WTC_LF_WR SERIES.pdf; Lifecycle: Comp-Approve; MATERIAL: CHIP; Manuf_PN: RR0510X-000-XN; Manuf_name: CYNTEC CO.. LTD.; Manuftr: CYN; Part_Type: *LF_Resistor; Status: Preferred; TOLERANCE: 5%; WATTAGE: 1/16W; fp_ECN: 0402 SERIES_LL34.xls
R12 R29 = R: RES CHIP 1K 1/16W +-1% (0402); CLASS: DISCRETE; CMPLS_LVL: EP; Data: WTC_LF_WR SERIES.pdf; Lifecycle: Comp-Approve; MATERIAL: CHIP; Manuf_PN: RR0510S-102-FN; Manuf_name: CYNTEC CO.. LTD.; Manuftr: CYN; Part_Type: *LF_Resistor; Status: Preferred; TOLERANCE: 1%; WATTAGE: 1/16W; fp_ECN: 0402 SERIES_LL34.xls
R13 R1263 = R: RES CHIP 200 1/16W +-1%(0402); CLASS: DISCRETE; CMPLS_LVL: EP; Data: WTC_LF_WR SERIES-4.pdf; From_pj: S79-C.Y.HUANG; Lifecycle: Comp-Approve; MATERIAL: CHIP; Manuf_PN: WR04X2000FTL; Manuf_name: WALSIN TECHNOLOGY CORPORATION; Manuftr: WTC; Part_Type: *LF_Resistor; TOLERANCE: 1%; WATTAGE: 1/16W; fp_ECN: 0402 SERIES_LL34.xls
R453 = R: RES CHIP 100 1/16W +-1%(0402); CLASS: DISCRETE; CMPLS_LVL: EP; Data: WTC_LF_WR SERIES.pdf; Lifecycle: Comp-Approve; MATERIAL: CHIP; Manuf_PN: RR0510S-101-FN; Manuf_name: CYNTEC CO.. LTD.; Manuftr: CYN; Part_Type: *LF_Resistor; Status: Preferred; TOLERANCE: 1%; WATTAGE: 1/16W; fp_ECN: 0402 SERIES_LL34.xls
R456 = R: RES CHIP 22 1/16W 5%(0402); CLASS: DISCRETE; CMPLS_LVL: EP; Data: CYN_LF_RL SERIES.pdf; From_pj: S57-HOWER; Lifecycle: Comp-Approve; MATERIAL: CHIP; Manuf_PN: RR0510S-220-JN; Manuf_name: CYNTEC CO.. LTD.; Manuftr: CYN; Part_Type: *LF_Resistor; Status: Preferred; TOLERANCE: 5%; WATTAGE: 1/16W; fp_ECN: 0402 SERIES_LL34.xls
U61 = NC7WZ17: IC(6P) 74LVC2G17GW (SC-88); CLASS: IC; CMPLS_LVL: EP; Data: 74LVC2G17.pdf; From_pj: T6S-LOUISE; Lifecycle: Comp-Approve; MATERIAL: IC; Manuf_name: PHILIPS TAIWAN LTD.,; Manuftr: PHI; Part_Type: *LF_Chipset; RD_CMPLS_LVL: EP
C65 C203 C207 = CAP_NP: CAP CHIP 0.1U 10V(+-10%.X7R.0402); CLASS: DISCRETE; CMPLS_LVL: EP; Data: RHT_LF_CAP SERIES-1.pdf; From_pj: S82-ICE; Lifecycle: Comp-Approve; MATERIAL: X7R; Manuf_PN: GRM155R71A104K; Manuf_name: "MURATA ERIE N.A. INC TAIWAN BRANCH Okayama Murata Mfg.Co..Ltd.Wakura Murata Mfg; Manuftr: MUR; Part_Type: *LF_C0402; Standard: ##; Status: Preferred; TOLERANCE: 10%; VOLTAGE: 10V; fp_ECN: 0402 SERIES_LL34.xls
CN2 = SCONN5_1051330011: CONN SMD MICRO USB 5P 1R FS(P0.65,H6.7); CLASS: IO; CMPLS_LVL: EP(V1); Data: MLX_SD-105133-011_REVB.pdf; From_pj: F06-RAYMOND; Lifecycle: Comp-Approve; MATERIAL: IO; Manuf_PN: 105133-0011; Manuf_name: MOLEX TAIWAN LTD.DONGGUAN MOLEX INTERCONNECT CO., LTD; Manuftr: MLX; Part_Type: *LF_Connector; RD_CMPLS_LVL: EP(V1)
U1 U2 = NC7SB3157: IC(6P) NC7SB3157P6X(SC70-6); CLASS: IC; CMPLS_LVL: EP; Data: NC7SB3157.pdf; From_pj: T52-NICK; Lifecycle: Comp-Approve; MATERIAL: IC; Manuf_PN: NC7SB3157P6X; Manuf_name: FAIRCHILD SEMICONDUCTOR; Manuftr: FAC; Part_Type: *LF_Chipset; Standard: Potential; Status: Normal
C270 C279 = CAP_NP: CAP CHIP 1U.6.3V(+-10%.X7R.0402); CLASS: DISCRETE; CMPLS_LVL: EP(V1); Data: MKP_LF_CAP SERIES.pdf; From_pj: T94-JEFF; Lifecycle: Comp-Approve; MATERIAL: X7R; Manuf_PN: MAG02X7R0J105K; Manuf_name: Matsuki Precision Ceramic Co.. Ltd.Matsuki Polymer Technology Co.. Ltd.; Manuftr: MKP; Part_Type: *LF_C0402; RD_CMPLS_LVL: EP(V1); TOLERANCE: 10%; VOLTAGE: 6.3V; fp_ECN: 0402 SERIES_LL34.xls
C276 = CAP_NP: CAP CHIP 0.01U 50V(+-10%,X7R,0402); CLASS: DISCRETE; CMPLS_LVL: EP(V1); Data: MUR_MLCC_20110826.pdf; From_pj: T2B-CHEESE; Lifecycle: Comp-Approve; MATERIAL: X7R; Manuf_PN: WBM155R71H103K; Manuf_name: MURATA ERIE N.A. INC TAIWAN BRANCH Okayama Murata Mfg.Co.,Ltd.; Manuftr: MUR; Part_Type: *LF_C0402; RD_CMPLS_LVL: EP(V1); TOLERANCE: 10%; VOLTAGE: 50V; fp_ECN: 0402 SERIES_LL34.xls
D13 = LED_0: LED SMD(2P) GREEN(LTST-C281PGKT-Q); CLASS: IC; CMPLS_LVL: EP(V1); Data: LIT_LTST-C281PGKT-Q.pdf; From_pj: MF1-TONY; Lifecycle: Comp-Approve; MATERIAL: IC; Manuf_PN: LTST-C281PGKT-Q; Manuf_name: LITEON ELECTRONIC CO., LTD.; Manuftr: LIT; Part_Type: *LF_Semiconductor; RD_CMPLS_LVL: EP(V1); Standard: End of Design; fp_ECN: BEGR0296Z01.msg
J13 = SCONN4_502280047N001: CONN SMD WAFER 4P 1R MR(P1,H2.9); CLASS: IO; CMPLS_LVL: EP(V1); Data: ACS_50224-0040N-001.pdf; From_pj: S5S-YVETTE; Lifecycle: Comp-Approve; MATERIAL: IO; Manuf_PN: 50224-0040N-001; Manuf_name: ACES ELECTRONIC CO., LTD.; Manuftr: ACS; Part_Type: *LF_Connector; RD_CMPLS_LVL: EP(V1)
R74 = R: RES CHIP 4.7K 1/16W +-5% (0402); BOM: AST2300; CLASS: DISCRETE; CMPLS_LVL: EP; Data: WTC_LF_WR SERIES.pdf; Lifecycle: Comp-Approve; MATERIAL: CHIP; Manuf_PN: RR0510S-472-JN; Manuf_name: CYNTEC CO.. LTD.; Manufacturer: RLC; Manuftr: CYN; Part_Type: *LF_Resistor; Status: Preferred; TOLERANCE: 5%; WATTAGE: 1/16W; fp_ECN: 0402 SERIES_LL34.xls; top_bot: BOT
R76 = R: RES CHIP 33.2 1/16W +-1%(0402); BOM: AST2300; CLASS: DISCRETE; CMPLS_LVL: EP; Data: CYN_LF_RL SERIES.pdf; From_pj: A06-EDISON; Lifecycle: Comp-Approve; MATERIAL: CHIP; Manuf_PN: RR0510S-33R2-FN; Manuf_name: CYNTEC CO.. LTD.; Manufacturer: CYN; Manuftr: CYN; Part_Type: *LF_Resistor; TOLERANCE: 1%; WATTAGE: 1/16W; fp_ECN: 0402 SERIES_LL34.xls
R77 = R: RES CHIP 4.7K 1/16W +-5% (0402); BOM: AST2300; CLASS: DISCRETE; CMPLS_LVL: EP; Data: WTC_LF_WR SERIES.pdf; Lifecycle: Comp-Approve; MATERIAL: CHIP; Manuf_PN: RR0510S-472-JN; Manuf_name: CYNTEC CO.. LTD.; Manufacturer: CYN; Manuftr: CYN; Not_insert: NI; Part_Type: *LF_Resistor; Status: Preferred; TOLERANCE: 5%; WATTAGE: 1/16W; fp_ECN: 0402 SERIES_LL34.xls
R298 = R: RES CHIP 4.7K 1/16W +-5% (0402); BOM: AST2300; CLASS: DISCRETE; CMPLS_LVL: EP; Data: WTC_LF_WR SERIES.pdf; Lifecycle: Comp-Approve; MATERIAL: CHIP; Manuf_PN: RR0510S-472-JN; Manuf_name: CYNTEC CO.. LTD.; Manufacturer: RLC; Manuftr: CYN; Part_Type: *LF_Resistor; Status: Preferred; TOLERANCE: 5%; WATTAGE: 1/16W; fp_ECN: 0402 SERIES_LL34.xls; top_bot: TOP
R454 = R: RES CHIP 4.7K 1/16W +-5% (0402); BOM: AST2300; CLASS: DISCRETE; CMPLS_LVL: EP; Data: WTC_LF_WR SERIES.pdf; Lifecycle: Comp-Approve; MATERIAL: CHIP; Manuf_PN: RR0510S-472-JN; Manuf_name: CYNTEC CO.. LTD.; Manuftr: CYN; Part_Type: *LF_Resistor; Status: Preferred; TOLERANCE: 5%; WATTAGE: 1/16W; fp_ECN: 0402 SERIES_LL34.xls
R512 = R: RES CHIP 220 1/16W +-1%(0402); CLASS: DISCRETE; CMPLS_LVL: EP; Data: TAI_LF_RM SERIES-2.pdf; From_pj: S2F-JOSEPH; Lifecycle: Comp-Approve; MATERIAL: CHIP; Manuf_PN: RM04FTN2200; Manuf_name: TA-I TECHNOLOGY CO..LTD.; Manufacturer: CYN; Manuftr: TAI; Part_Type: *LF_Resistor; TOLERANCE: 1%; WATTAGE: 1/16W; fp_ECN: 0402 SERIES_LL34.xls; top_bot: TOP
R523 = R: RES CHIP 10K 1/16W +-1% (0402); BOM: AST2300; CLASS: DISCRETE; CMPLS_LVL: EP; Data: WTC_LF_WR SERIES.pdf; From_pj: S82; Lifecycle: Comp-Approve; MATERIAL: CHIP; Manuf_PN: RR0510S-103-FN; Manuf_name: CYNTEC CO.. LTD.; Manufacturer: RLC; Manuftr: CYN; Part_Type: *LF_Resistor; Status: Preferred; TOLERANCE: 1%; WATTAGE: 1/16W; fp_ECN: 0402 SERIES_LL34.xls; top_bot: TOP
R524 = R: RES CHIP 10 1/16W +-1%(0402); BOM: AST2300; CLASS: DISCRETE; CMPLS_LVL: EP; Data: TAI_LF_RM SERIES-3.pdf; From_pj: RS2-MATT; MATERIAL: CHIP; Manuf_PN: RM04FTN10R0; Manuf_name: TA-I TECHNOLOGY CO..LTD.; Manufacturer: CYN; Manuftr: TAI; Part_Type: *LF_Resistor; TOLERANCE: 1%; WATTAGE: 1/16W; fp_ECN: 0402 SERIES_LL34.xls
R794 R795 = R: RES CHIP 33.2 1/16W +-1%(0402); CLASS: DISCRETE; CMPLS_LVL: EP; Data: CYN_LF_RL SERIES.pdf; From_pj: A06-EDISON; Lifecycle: Comp-Approve; MATERIAL: CHIP; Manuf_PN: RR0510S-33R2-FN; Manuf_name: CYNTEC CO.. LTD.; Manufacturer: RHT; Manuftr: CYN; Part_Type: *LF_Resistor; TOLERANCE: 1%; WATTAGE: 1/16W; fp_ECN: 0402 SERIES_LL34.xls; top_bot: TOP
OSC1 = OSC4_SIT1602BI7233E25000000D: OSC SMD 25MHZ(25PPM,3.3V)SIT1602BI; CLASS: IO; Data: SIM_SIT1602BI-72-33E-25.000000D.pdf; From_pj: XG1-TONY; Lifecycle: P/N Release; MATERIAL: MISC; Manuf_PN: SIT1602BI-72-33E-25.000000D; Manuf_name: Sitime Corporation.; Manuftr: SIM; Part_Type: *LF_Misc; RD_CMPLS_LVL: EP(V1); Standard: Non-Preferred
R62 = R: RESISTOR CHIP 0 1/16W +-5%(0402); BOM: TI; CLASS: DISCRETE; CMPLS_LVL: EP; Data: WTC_LF_WR SERIES.pdf; Lifecycle: Comp-Approve; MATERIAL: CHIP; Manuf_PN: RR0510X-000-XN; Manuf_name: CYNTEC CO.. LTD.; Manuftr: CYN; Not_insert: NI; Part_Type: *LF_Resistor; Status: Preferred; TOLERANCE: 5%; WATTAGE: 1/16W; fp_ECN: 0402 SERIES_LL34.xls
R531 = R: RES CHIP 4.7K 1/16W +-5% (0402); CLASS: DISCRETE; CMPLS_LVL: EP; Data: WTC_LF_WR SERIES.pdf; Lifecycle: Comp-Approve; MATERIAL: CHIP; Manuf_PN: RR0510S-472-JN; Manuf_name: CYNTEC CO.. LTD.; Manufacturer: RLC; Manuftr: CYN; Part_Type: *LF_Resistor; Status: Preferred; TOLERANCE: 5%; WATTAGE: 1/16W; fp_ECN: 0402 SERIES_LL34.xls; top_bot: TOP
R538 = R: RES CHIP 4.7K 1/16W +-5% (0402); CLASS: DISCRETE; CMPLS_LVL: EP; Data: WTC_LF_WR SERIES.pdf; Lifecycle: Comp-Approve; MATERIAL: CHIP; Manuf_PN: RR0510S-472-JN; Manuf_name: CYNTEC CO.. LTD.; Manufacturer: RLC; Manuftr: CYN; Not_insert: NI; Part_Type: *LF_Resistor; Status: Preferred; TOLERANCE: 5%; WATTAGE: 1/16W; fp_ECN: 0402 SERIES_LL34.xls; top_bot: TOP
U25 = NL17SZ08DFT2G: IC OTHER  (5P) NL17SZ08DFT2G (SOT-353); CLASS: IC; CMPLS_LVL: EP(V1); Data: ONS_NL17SZ08DFT2G.pdf; From_pj: JBEF-STAN; Lifecycle: Comp-Approve; MATERIAL: IC; Manuf_name: ON SEMICONDUCTOR; Manuftr: ONS; Part_Type: *LF_Chipset; RD_CMPLS_LVL: EP(V1)
U14 = LM4FB15P9ZADHIN: PROG IC CTRL(212P)XM4E129BNCZADI2(BGA); CLASS: IC; Data: TIC_TM4E129BNCZAD.pdf; From_pj: S1M-MARK; Lifecycle: Comp-Release Qty; MATERIAL: IC; Manuf_name: TEXAS INSTRUMENTS SUPPLY CO.,; Manuftr: TIC; Part_Type: *LF_Chipset; RD_CMPLS_LVL: EP(V1); Standard: Potential

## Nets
GND: C49.1 C50.2 C51.2 C65.2 C83.1 C94.1 C96.1 C108.2 C203.2 C207.2 C232.1 C234.1 C235.1 C252.2 C270.2 C276.2 C279.2 C290.2 C386.1 C630.1 CN2.4(ID) CN2.5(GND) CN2.G1 CN2.G2 CN2.G3 J13.G1 J13.G2 J43.A1(GND) J43.A11(GND) J43.A21(GND) J43.A31(GND) J43.A38 J43.B1(GND) J43.B11(GND) J43.B21(GND) J43.B31(GND) J43.B38 J43.C1(GND) J43.C2 J43.C5 J43.C8 J43.C11(GND) J43.C14 J43.C18 J43.C21(GND) J43.C24 J43.C25 J43.C28 J43.C31(GND) J43.D1(GND) J43.D2 J43.D5 J43.D8 J43.D11(GND) J43.D14 J43.D18 J43.D21(GND) J43.D24 J43.D25 J43.D28 J43.D31(GND) J43.G1 J43.G2 J43.G3 J43.G4 OSC1.2(GND) R62.1 R77.2 R448.2 R452.2 R521.1 R523.2 R538.2 R810.1 U1.2(GND) U2.2(GND) U8.4(GND) U9.2(GND) U14.D18(GNDX2) U14.G5(VREFA-) U14.R18(GNDX) U17.4(GND) U24.2(GND) U25.3(GND) U33.3(GND) U35.3(GND) U41.3(GND) U60.4(VSS) U61.2(GND) U95.2(GND) ; also on sheet 1 2 3 4 11 12 13 14 15 16 17 18 19 20 22 23 24 25 26 27 28 31 32 41 42 45 46 47 48 49 50 51 52 53 54 55 56 57 58 59 60 61 62 63 64 73 74 75 77 79 81 82 83 84 86 87 88 92
P1V05_COMBINED: C270.1 U14.C8(PJ0/PECIVTT) ; also on sheet 1 3 4 16 18 19 41 42 45 47 48 50 51 52 54 55 56 63 74 75 79 84 92 94
P1V05_COMBINED_AST_SCALED: U14.A4(PD4/AIN7) ; also on sheet 74
P1V05_PCH: R577.1 ; also on sheet 50 51 52 63 74 84
P1V05_PCH_AST_SCALED: U14.B3(PD6/AIN5) ; also on sheet 74
P3V3: C386.2 R1361.1 U33.5(VCC) ; also on sheet 4 19 20 32 41 42 46 47 49 50 52 55 56 63 74 77 81
P3V3_AST_SCALED: U14.H3(PE0/AIN3) ; also on sheet 74
P3V3_STBY: C49.2 C65.1 C83.2 C94.2 C96.2 C108.1 C203.1 C207.1 C232.2 C234.2 C235.2 C252.1 C276.1 C279.1 C290.1 C630.2 D13.A OSC1.4(VDD) R12.2 R29.2 R51.1 R61.2 R74.2 R153.1 R173.1 R298.2 R325.1 R437.1 R447.1 R454.1 R465.1 R466.1 R467.1 R471.1 R475.1 R476.1 R519.1 R520.1 R531.1 R600.1 R854.1 R856.1 R1261.2 R1262.2 R1314.1 R1315.1 R1316.1 R1317.1 R1338.1 R1349.2 U1.5(VCC) U2.5(VCC) U8.8(V+) U9.5(VCC) U14.F4(VREFA+) U17.8(V+) U24.5(VCC) U25.5(VCC) U35.5(VCC) U41.5(VCC) U60.8(VCC) U61.5(VCC) U95.5(VCC) ; also on sheet 3 4 13 14 16 18 19 20 22 24 25 26 27 28 31 32 41 52 55 56 57 58 59 62 63 64 73 74 75 77 79 81 82 84 86 87 88 92
P3V3_STBY_AST_SCALED: U14.B2(PD7/AIN4) ; also on sheet 74
P3V_BAT: U14.P19(VBAT) ; also on sheet 13 18 41 52 63
P3V_BAT_AST_SCALED: U14.B4(PD5/AIN6) ; also on sheet 74
P5V_STBY: CN2.1(VBUS) ; also on sheet 1 2 13 23 26 31 74 84
P5V_STBY_AST_SCALED: U14.H2(PE1/AIN2) ; also on sheet 74
P5V_STBY_DETECT: U14.V16(PK6/I2C4SCL) ; also on sheet 74
P12V_AST_SCALED: U14.G2(PE3/AIN0) ; also on sheet 74
PVCCIN_VRHOT_N: U14.A8(PP7/GPIOPP7) U25.1(INB) ; also on sheet 3
PVDDR_VRHOT_N: U14.D8(PP4/GPIOPP4) U25.2(INA) ; also on sheet 24
PVDDRA_AST_SCALED: U14.G1(PE2/AIN1) ; also on sheet 74
BATLOW_N: R1348.1 R1349.1 U14.L2(PC6/FAN0PWM1) ; also on sheet 20 64
BATLOW_N_R: J43.A27 R1348.2
BATTERY_DETECT: U14.W16(PK7/I2C4SDA) ; also on sheet 74
BIOS_DIS0_N: J43.A34 ; also on sheet 82
BMC_BYPASS_SELECT: R61.1 R62.2 U14.P18(RESET_N)
BMC_COM_SW_N: R437.2 U1.6(S) U2.6(S) U14.W10(PT0/GPIOPT0)
BMC_HARTBEAT_LED_R: R512.2 U14.T13(PS5/GPIOPS5)
BMC_HEARTBEAT_LED: D13.C R512.1
BMC_PWR_BTN_OUT_N: R628.2 R1157.1 ; also on sheet 47
BMC_PWR_BTN_OUT_N_R: R1157.2 U14.K2(PK3/GPIOPK3)
BMC_READY_N: R531.2 R538.1 U14.F16(PJ3/GPIOPJ3) ; also on sheet 47
BMC_RST_BTN_OUT_N: U14.B6(PB5/I2C5SDA) ; also on sheet 73 81
BMC_SPICLK_R: R516.1 U14.E3(PQ0/SSI3CLK)
BMC_SPICS0_N_R: R79.1 U14.E2(PQ1/SSI3FSS)
BMC_SPIMISO_R: R72.1 U14.M4(PQ3/SSI3XDAT1)
BMC_SPIMOSI_R: R513.1 U14.H4(PQ2/SSI3XDAT0)
BMC_TI_PECI: R523.1 R524.2 ; also on sheet 47
BMC_TI_PECI_R: R524.1 U14.E7(PJ1/PECI0SD)
CARRIER_BOARD_PWR_OK: R1404.2 ; also on sheet 82
CARRIER_BOARD_PWR_OK_R: J43.B24 R1404.1
CLK_25M_MINIBMC_CLKIN: OSC1.3(OUT) R44.1
CLK_25M_MINIBMC_CLKIN_R: R44.2 U14.E19(OSC0)
CLK_33M_COME_LPC: J43.B10 ; also on sheet 49
CLK_33M_TI_LPC: U14.H19(PL1/LPC0CLK) ; also on sheet 49
COME_GPI0_BUF: U14.B14(PS2/GPIOPS2) ; also on sheet 20
FAST_THROTTLE_N: J43.B35 R1337.1
FAST_THROTTLE_N_R: R1337.2 R1338.2 U14.W7(PF5/FAN0TACH4) ; also on sheet 47 64
FM_BDE_POST_CMPLT_N: R325.2 R331.2 U14.A14(PS3/GPIOPS3)
FM_BDE_POST_CMPLT_R_N: R331.1 U41.4(Y)
FM_BDXDE_CATERR_LVT3_N: U14.H18(PL4/LPC0SCI_N) ; also on sheet 47 56 64
FM_BDXDE_ERR0_LVT3_N: U14.E17(PJ5/GPIOPJ5) ; also on sheet 47 56 64
FM_BDXDE_ERR1_LVT3_N: U14.N1(PJ6/GPIOPJ6) ; also on sheet 47 56 64
FM_BDXDE_ERR2_LVT3_N: U14.K5(PJ7/GPIOPJ7) ; also on sheet 56 64
FM_BDXDE_SLP3_BUF_N: J43.A15 ; also on sheet 20
FM_BDXDE_SLP3_N: U14.V9(PS4/GPIOPS4) ; also on sheet 14 20 63 64
FM_BDXDE_SLP4_BUF_N: J43.A18 ; also on sheet 20
FM_BDXDE_SLP4_N: U14.V6(PF1/FAN0TACH2) ; also on sheet 20 63 64
FM_BDXDE_SMI_N: U24.1(1A) ; also on sheet 47 63
FM_BDXDE_THERMTRIP_PCH_N: R841.2 ; also on sheet 47
FM_BDXDE_THERMTRIP_PCH_R_N: R577.2 R841.1 U35.4(Y)
FM_BIOS_POST_CMPLT_N: R854.2 U41.2(A) ; also on sheet 47
FM_CPLD_BDXDE_THERMTRIP_N: J43.A35 U14.K1(PK2/GPIOPK2) ; also on sheet 56 64
FM_CPLD_CLEAR_LATCH: U14.W9(PR6/U1TX) ; also on sheet 64
FM_CPLD_CPU_DIMM_EVENT_CO_N: U14.M3(PQ7/GPIOPQ7) ; also on sheet 19 64
FM_CPLD_FIVR_FAULT: U14.F18(PJ4/GPIOPJ4) ; also on sheet 56 64
FM_CPLD_PCH_THERMTRIP_N: U35.2(A) ; also on sheet 64
FM_CPLD_THERMTRIP_N_LATCH: U14.K3(PC7/FAN0TACH1) ; also on sheet 64
FM_CPLD_VR_HOT_N: R168.2 ; also on sheet 64
FM_CPLD_VR_HOT_R_N: R168.1 U25.4(OUTY)
FM_CPU_THROTTLE_N: R1361.2 U33.2(A) ; also on sheet 46
FM_CPU_THROTTLE_N_R1: R600.2 U33.4(Y) ; also on sheet 64
FM_FAST_PROCHOT_BMC_N: U14.A7(PE6/SGPMO) ; also on sheet 55
FM_FAST_PROCHOT_N: U14.D6(PP0/SGPMCLK) ; also on sheet 14 55
FM_FORCE_BMC_UPDATE: R74.1 R77.1 U14.M2(PC4/FAN0PWM0)
FM_NMI_EVENT_BMC_N: R173.2 R850.2 U14.B7(PE7/NMI)
FM_NMI_EVENT_BMC_R_N: R850.1 U24.4(2Y)
FM_NMI_EVENT_N_NOA_CLK2: U24.3(2A) ; also on sheet 47 63
FM_PCH_HOT_LVT3_N: U14.D7(PP1/SGPMLD) ; also on sheet 56 64
FM_PWR_LED_N: U14.R10(PR7/GPIOPR7) ; also on sheet 77
FM_SMI_BMC_N: R153.2 R849.2 U14.V7(PF4/FAN0PWM4)
FM_SMI_BMC_R_N: R849.1 U24.6(1Y)
FM_USB_OC_0_N: R1189.1 ; also on sheet 16 46
FM_USB_OC_0_N_R: R1189.2 U95.6(1Y)
FM_USB_OC_1_N: R1190.1 ; also on sheet 16 46
FM_USB_OC_1_N_R: R1190.2 U95.4(2Y)
FP_PWR_BTN_BUF_N: R456.2 R628.1 U14.U12(PN7/GPIOPN7) ; also on sheet 64 73
FP_PWR_BTN_N_RR: PR158.2 R12.1 R13.1 U9.6(1Y)
FP_PWR_BTN_N_RRR: C50.1 R13.2 U61.3(A2)
FP_PWR_BTN_R_N: R456.1 U61.4(Y2)
FP_RST_BTN_BUF_N: R453.2 R454.2 U14.C6(PB4/I2C5SCL) ; also on sheet 64
FP_RST_BTN_R_N: R453.1 U61.6(Y2)
FRU_ADDR0: R447.2 U60.1(E0)
FRU_ADDR1: R452.1 U60.2(E1)
FRU_ADDR2: R448.1 U60.3(E2)
IRQ_BMC_PCH_NMI_NOA1_CLK: R298.1 U14.G19(PL5/LPC0PD_N) ; also on sheet 47
IRQ_IBMC_PCH_SMI_LPC_N: U14.N15(PG0/FAN0PWM6) ; also on sheet 47 63
IRQ_ILB_SEIRQ_BMC: R34.1 R856.2 ; also on sheet 19
IRQ_TI_SERIRQ: R34.2 U14.J18(PL3/LPC0SERIRQ)
JTAG_CPLD_TCK: U14.B11(PN1/U1CTS) ; also on sheet 14
JTAG_CPLD_TDI: U14.A11(PN2/U1DCD) ; also on sheet 14
JTAG_CPLD_TDO: U14.B10(PN3/U1DSR) ; also on sheet 14
JTAG_CPLD_TMS: U14.A10(PN4/U1DTR) ; also on sheet 14
JTAG_TI_TCK: J13.4 R476.2 R477.2
JTAG_TI_TCK_R: R477.1 U14.B15(PC0/TCK/SWDCLK)
JTAG_TI_TDI: J13.3 R474.2 R475.2
JTAG_TI_TDI_R: R474.1 U14.D14(PC2/TDI)
JTAG_TI_TDO: J13.2 R473.2
JTAG_TI_TDO_R: R473.1 U14.C14(PC3/TDO/SWO)
JTAG_TI_TMS: J13.1 R469.2 R471.2
JTAG_TI_TMS_R: R469.1 U14.C15(PC1/TMS/SWDIO)
LAN_I210_MDI0_N: J43.A12 ; also on sheet 87
LAN_I210_MDI0_P: J43.A13 ; also on sheet 87
LAN_I210_MDI1_N: J43.A9 ; also on sheet 87
LAN_I210_MDI1_P: J43.A10 ; also on sheet 87
LAN_I210_MDI2_N: J43.A6 ; also on sheet 87
LAN_I210_MDI2_P: J43.A7 ; also on sheet 87
LAN_I210_MDI3_N: J43.A2 ; also on sheet 87
LAN_I210_MDI3_P: J43.A3 ; also on sheet 87
LED0_LAN_SPEED: U14.E18(PT2/GPIOPT2) ; also on sheet 92
LED0_NIC_LINK_ACT_N: U14.F17(PT3/GPIOPT3) ; also on sheet 92
LED_I210_LED0_N: J43.B2 ; also on sheet 87
LED_I210_LED1_N: J43.A4 ; also on sheet 87
LED_I210_LED2_N: J43.A5 ; also on sheet 87
LPC_FRAME_N: J43.B3 R37.1 ; also on sheet 47
LPC_LAD0: J43.B4 R43.1 ; also on sheet 47
LPC_LAD1: J43.B5 R47.1 ; also on sheet 47
LPC_LAD2: J43.B6 R39.1 ; also on sheet 47
LPC_LAD3: J43.B7 R36.1 ; also on sheet 47
LPC_TI_FRAME_N: R37.2 U14.G16(PL0/LPC0FRAME_N)
NC_LPC_CLKRUN_N: U14.G18(PL2/LPC0CLKRUN_N)
P3E_E_RX_DN<2>: J43.C20 ; also on sheet 94
P3E_E_RX_DN<3>: J43.C23 ; also on sheet 94
P3E_E_RX_DP<2>: J43.C19 ; also on sheet 94
P3E_E_RX_DP<3>: J43.C22 ; also on sheet 94
P3E_E_TX_DN<2>: J43.D20 ; also on sheet 94
P3E_E_TX_DN<3>: J43.D23 ; also on sheet 94
P3E_E_TX_DP<2>: J43.D19 ; also on sheet 94
P3E_E_TX_DP<3>: J43.D22 ; also on sheet 94
PORT80_LED0: U14.P4(PH0/LPC0COMXRTS) ; also on sheet 77
PORT80_LED1: U14.R2(PH1/LPC0COMXCTS) ; also on sheet 77
PORT80_LED2: U14.R1(PH2/LPC0COMXDCD) ; also on sheet 77
PORT80_LED3: U14.T1(PH3/LPC0COMXDSR) ; also on sheet 77
PORT80_LED4: U14.R3(PH4/LPC0COMXDTR) ; also on sheet 77
PORT80_LED5: U14.T2(PH5/LPC0COMXRI) ; also on sheet 77
PORT80_LED6: U14.U2(PH6/GPIOPH6) ; also on sheet 77
PORT80_LED7: U14.V2(PH7/GPIOPH7) ; also on sheet 77
PU_25M_BMC_CLK_EN_R: OSC1.1(OE||ST_N||NC) R51.2
PWR_BTN_COME_BUF_N: PR158.1 ; also on sheet 82
PWR_BTN_COME_N: J43.B12 ; also on sheet 82
PWR_BTN_XDP: U9.1(1A) ; also on sheet 16 54
PWRGD_CPU0_CPLD: U14.M1(PC5/FAN0TACH0) ; also on sheet 56 64
PWRGD_PCH_PWROK: U14.A5(PE4/FAN0TACH7) ; also on sheet 13 14 47
PWRGD_PVCCIN: U14.T14(PG1/FAN0TACH6) ; also on sheet 3 64
RSM_RST_N: U14.R13(PS7/GPIOPS7) ; also on sheet 14 47
RST_BTN_COME_BUF_N: R25.1 ; also on sheet 82
RST_BTN_XDP: U9.3(2A) ; also on sheet 16 54
RST_PLTRST_BMC_N: U14.D13(PS1/LPC0RESET_N) ; also on sheet 58
RST_PLTRST_N: U41.1(OE) ; also on sheet 47 62 64
RST_SYS_RESET_R_N: R25.2 R29.1 R1263.1 U9.4(2Y)
RST_SYS_RESET_RR_N: C51.1 R1263.2 U61.1(A2)
SATA_RX_C_DN<0>: C199.2 J43.A20
SATA_RX_C_DP<0>: C202.2 J43.A19
SATA_RX_DN<0>: C199.1 ; also on sheet 46
SATA_RX_DP<0>: C202.1 ; also on sheet 46
SATA_TX_C_DN<0>: C511.2 J43.A17
SATA_TX_C_DP<0>: C519.2 J43.A16
SATA_TX_DN<0>: C511.1 ; also on sheet 46
SATA_TX_DP<0>: C519.1 ; also on sheet 46
SLP_SUS_STAT_BUF_N: J43.B18 ; also on sheet 82
SLP_SUS_STAT_N: U14.F2(PB6/I2C6SCL) ; also on sheet 63 82
SMB_BMC_3V3SB_ALRT_N: U14.T8(PF6/FAN0PWM5) ; also on sheet 13 73
SMB_BMC_3V3SB_CLK: J43.B33 ; also on sheet 73
SMB_BMC_3V3SB_CLK_R: U14.D2(PD2/I2C8SCL) ; also on sheet 73
SMB_BMC_3V3SB_DAT: J43.B34 ; also on sheet 73
SMB_BMC_3V3SB_DAT_R: U14.D1(PD3/I2C8SDA) ; also on sheet 73
SMB_HOST_3V3SB_CLK: U14.A17(PB2/I2C0SCL) ; also on sheet 73
SMB_HOST_3V3SB_DAT: U14.B17(PB3/I2C0SDA) ; also on sheet 73
SMB_HOST_XDP_CLK: R794.1 ; also on sheet 18 54 62 73
SMB_HOST_XDP_CLK_R: R794.2 U14.B12(PP5/I2C2SCL)
SMB_HOST_XDP_DAT: R795.1 ; also on sheet 18 54 62 73
SMB_HOST_XDP_DAT_R: R795.2 U14.B8(PP6/I2C2SDA)
SMB_INA230_ALRT_N_PROCHOT: U14.B5(PE5/FAN0PWM7/GPIO) ; also on sheet 64 86
SMB_SENSOR_3V3SB_CLK: R1425.2 ; also on sheet 73
SMB_SENSOR_3V3SB_CLK_R: U14.N5(PR0/I2C1SCL) ; also on sheet 73
SMB_SENSOR_3V3SB_CLK_R1: R1423.2 R1426.1 ; also on sheet 73
SMB_SENSOR_3V3SB_DAT: R1424.2 ; also on sheet 73
SMB_SENSOR_3V3SB_DAT_R: U14.N4(PR1/I2C1SDA) ; also on sheet 73
SMB_SENSOR_3V3SB_DAT_R1: R1422.2 R1427.1 ; also on sheet 73
SMB_SENSOR_FRU_3V3SB_CLK: R1426.2 U60.6(SCL)
SMB_SENSOR_FRU_3V3SB_DAT: R1427.2 U60.5(SDA)
SMB_SENSOR_TMP1_3V3SB_CLK: R1423.1 U17.2(SCL)
SMB_SENSOR_TMP1_3V3SB_DAT: R1422.1 U17.1(SDA)
SMB_SENSOR_TMP2_3V3SB_CLK: R1425.1 U8.2(SCL)
SMB_SENSOR_TMP2_3V3SB_DAT: R1424.1 U8.1(SDA)
SMB_SML0_3V3SB_CLK_R: U14.C2(PD0/I2C7SCL) ; also on sheet 73
SMB_SML0_3V3SB_DAT_R: U14.C1(PD1/I2C7SDA) ; also on sheet 73
SPI_BMC_PCH_CLK: R516.2 ; also on sheet 59
SPI_BMC_PCH_CS0_N: R79.2 ; also on sheet 59
SPI_BMC_PCH_MISO: R72.2 ; also on sheet 59
SPI_BMC_PCH_MOSI: R513.2 ; also on sheet 59
SPI_SW_SELECT: U14.V10(PT1/GPIOPT1) ; also on sheet 59
SVR_ID0: R1314.2 U14.N2(PR2/GPIOPR2)
SVR_ID1: R1315.2 U14.V8(PR3/GPIOPR3)
SVR_ID2: R1316.2 U14.P3(PR4/GPIOPR4)
SVR_ID3: R1317.2 U14.P2(PR5/U1RX)
TI_LAD0_R: R43.2 U14.L19(PM3/LPC0AD0)
TI_LAD1_R: R47.2 U14.L18(PM2/LPC0AD1)
TI_LAD2_R: R39.2 U14.K19(PM1/LPC0AD2)
TI_LAD3_R: R36.2 U14.K18(PM0/LPC0AD3)
TMP_A0_0: R521.2 U17.7(A0)
TMP_A0_1: R467.2 U8.7(A0)
TMP_A1_0: R519.2 U17.6(A1)
TMP_A1_1: R466.2 U8.6(A1)
TMP_A2_0: R520.2 U17.5(A2)
TMP_A2_1: R465.2 U8.5(A2)
TP_BMC_ID_BTN_IN_N: U14.U10(PS6/GPIOPS6)
TP_NCSI_SEL_BMC: U14.U8(PF7/FAN0TACH5)
TP_NCSI_TI_50M_CLK: U14.M18(PM4/RMII0-EN0RREF_CLK)
TP_NCSI_TI_CRS_DV: U14.U14(PG7/RMII0-EN0RXDV)
TP_NCSI_TI_RXD0: U14.W12(PQ5/RMII0-EN0RXD0)
TP_NCSI_TI_RXD1: U14.U15(PQ6/RMII0-EN0RXD1)
TP_NCSI_TI_RXER: U14.V12(PG6/RMII0-EN0RXER)
TP_NCSI_TI_TX_EN: U14.M16(PG3/RMII0-EN0TXEN)
TP_NCSI_TI_TXD0: U14.K17(PG4/RMII0-EN0TXD0)
TP_NCSI_TI_TXD1: U14.K15(PG5/RMII0-EN0TXD1)
TP_U3_ALERT: U17.3(ALERT)
TP_U55_ALERT: U8.3(ALERT)
U60_FRU_WC_N: R810.2 U60.7(~{WC})
UART_BDE_TI_RX: R1402.1 ; also on sheet 19
UART_BDE_TI_RX_R: R1402.2 U2.1(B1)
UART_BDE_TI_TX: U1.1(B1) ; also on sheet 19
UART_DEBUG_RX: R1401.1 U2.4(A)
UART_DEBUG_RX_R: CN2.3(D+) R1401.2
UART_DEBUG_TX: CN2.2(D-) R1252.2
UART_DEBUG_TX_R: R1252.1 U1.4(A)
UART_TI_R_TXD: R76.1 U14.J2(PK1/U4TX)
UART_TI_RXD: R1417.1 U14.J1(PK0/U4RX)
UART_TI_RXD_R: R1417.2 U2.3(B0)
UART_TI_TXD: R76.2 U1.3(B0)
USB3_RX_P1_DN: J43.C3 ; also on sheet 46
USB3_RX_P1_DP: J43.C4 ; also on sheet 46
USB3_RX_P2_DN: J43.C6 ; also on sheet 46
USB3_RX_P2_DP: J43.C7 ; also on sheet 46
USB3_TX_P1_DN: J43.D3 ; also on sheet 46
USB3_TX_P1_DP: J43.D4 ; also on sheet 46
USB3_TX_P2_DN: J43.D6 ; also on sheet 46
USB3_TX_P2_DP: J43.D7 ; also on sheet 46
USB_0_1_OC_N: R1187.2 R1261.1 ; also on sheet 13
USB_0_1_OC_N_R: R1187.1 U95.1(1A)
USB_2_3_OC_N: R1191.2 R1262.1 ; also on sheet 13
USB_2_3_OC_N_R: R1191.1 U95.3(2A)
XDP_CPU_SYSPWROK: U14.U6(PF0/FAN0PWM2) ; also on sheet 14 16 47 54

Not connected (* = marked no-connect by the designer): J43 A8* A14* A22* A23* A24* A25* A26* A28* A29* A30* A32* A33* A36* A37* A39* A40* B8* B9* B13* B14* B15* B16* B17* B19* B20* B22* B23* B25* B26* B27* B28* B29* B30* B32* B36* B37* B39* B40* C9* C10* C12* C13* C15* C16* C17* C26* C27* C29* C30* C32* C33* C34* C35* C36* C37* C38* C39* C40* D9* D10* D12* D13* D15* D16* D17* D26* D27* D29* D30* D32* D33* D34* D35* D36* D37* D38* D39* D40*; U14 A13(PQ4/DIVSCLK)* A16(PB0/USB0ID)* B9(PN5/U1RI)* B13(PP2/USB0NXT)* B16(PB1/USB0VBUS)* B18(PL7/USB0DM)* C10(PN0/U1RTS)* C12(PP3/RTCCLK)* C18(PL6/USB0DP)* D12(PS0/GPIOPS0)* D19(OSC1)* F1(PB7/I2C6SDA)* G15(PM5/SGPMI)* H17(PJ2/GPIOPJ2)* M17(HIB_N)* N18(PM7/EN0COL)* N19(PM6/EN0CRS)* R7(PA7/USB0EPEN)* T6(PA2/SSI0CLK)* T7(PF3/RMII0-EN0MDIO)* T12(PN6/EN0TXER)* T18(XOSC0)* T19(XOSC1)* U5(PA3/SSI0FSS)* U18(WAKE_N)* U19(PK4/I2C3SCL)* V3(PA0/U0Rx)* V4(PA4/SSI0XDAT0)* V5(PA6/EN0RXCK)* V11(PG2/EN0TXCK)* V17(PK5/I2C3SDA)* W3(PA1/U0Tx)* W4(PA5/SSI0XDAT1)* W6(PF2/RMII0-EN0MDC)*; U33 1(NC)*; U35 1(NC)*

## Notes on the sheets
sheet 65
- COM-E_TYPE7_AB_1
sheet 66
- COM-E CONN CD_1
- GOLDEN_FINGER
sheet 67
- LEVEL_SHIFT
sheet 68
- FRU
- ADDRESS 0XA2
- ADDRESS 0X9C
- ADDRESS 0X9E
- SYS_SENSOR
sheet 69
- PWR and SYS RESET Button
sheet 70
- DESIGN NOTE :
  LOW B0 to A
  HIGH B1 to A
- SOC
- TI
- SOC
- TI
- DEBUG UART
sheet 71
- FM_FORCE_BMC_UPDATE
  High <-- default
  Low  <-- BMC update mode
- Check this voltage
- SNOWFLAKE_1
sheet 72
- need to connect to PCH
- DESIGN NOTE : PWRBTN PASS THROUGH BRIDGE IC.
- BOM NOTE:
  BMC_BYPASS_SELECT
  Low  <-- Bypass BMC
  High <-- BMC EN (default)
- SNOWFLAKE_2
